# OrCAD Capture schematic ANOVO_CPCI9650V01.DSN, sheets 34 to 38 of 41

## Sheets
34 -DUAL POWER: size C; title: 34--CPCI hot swap
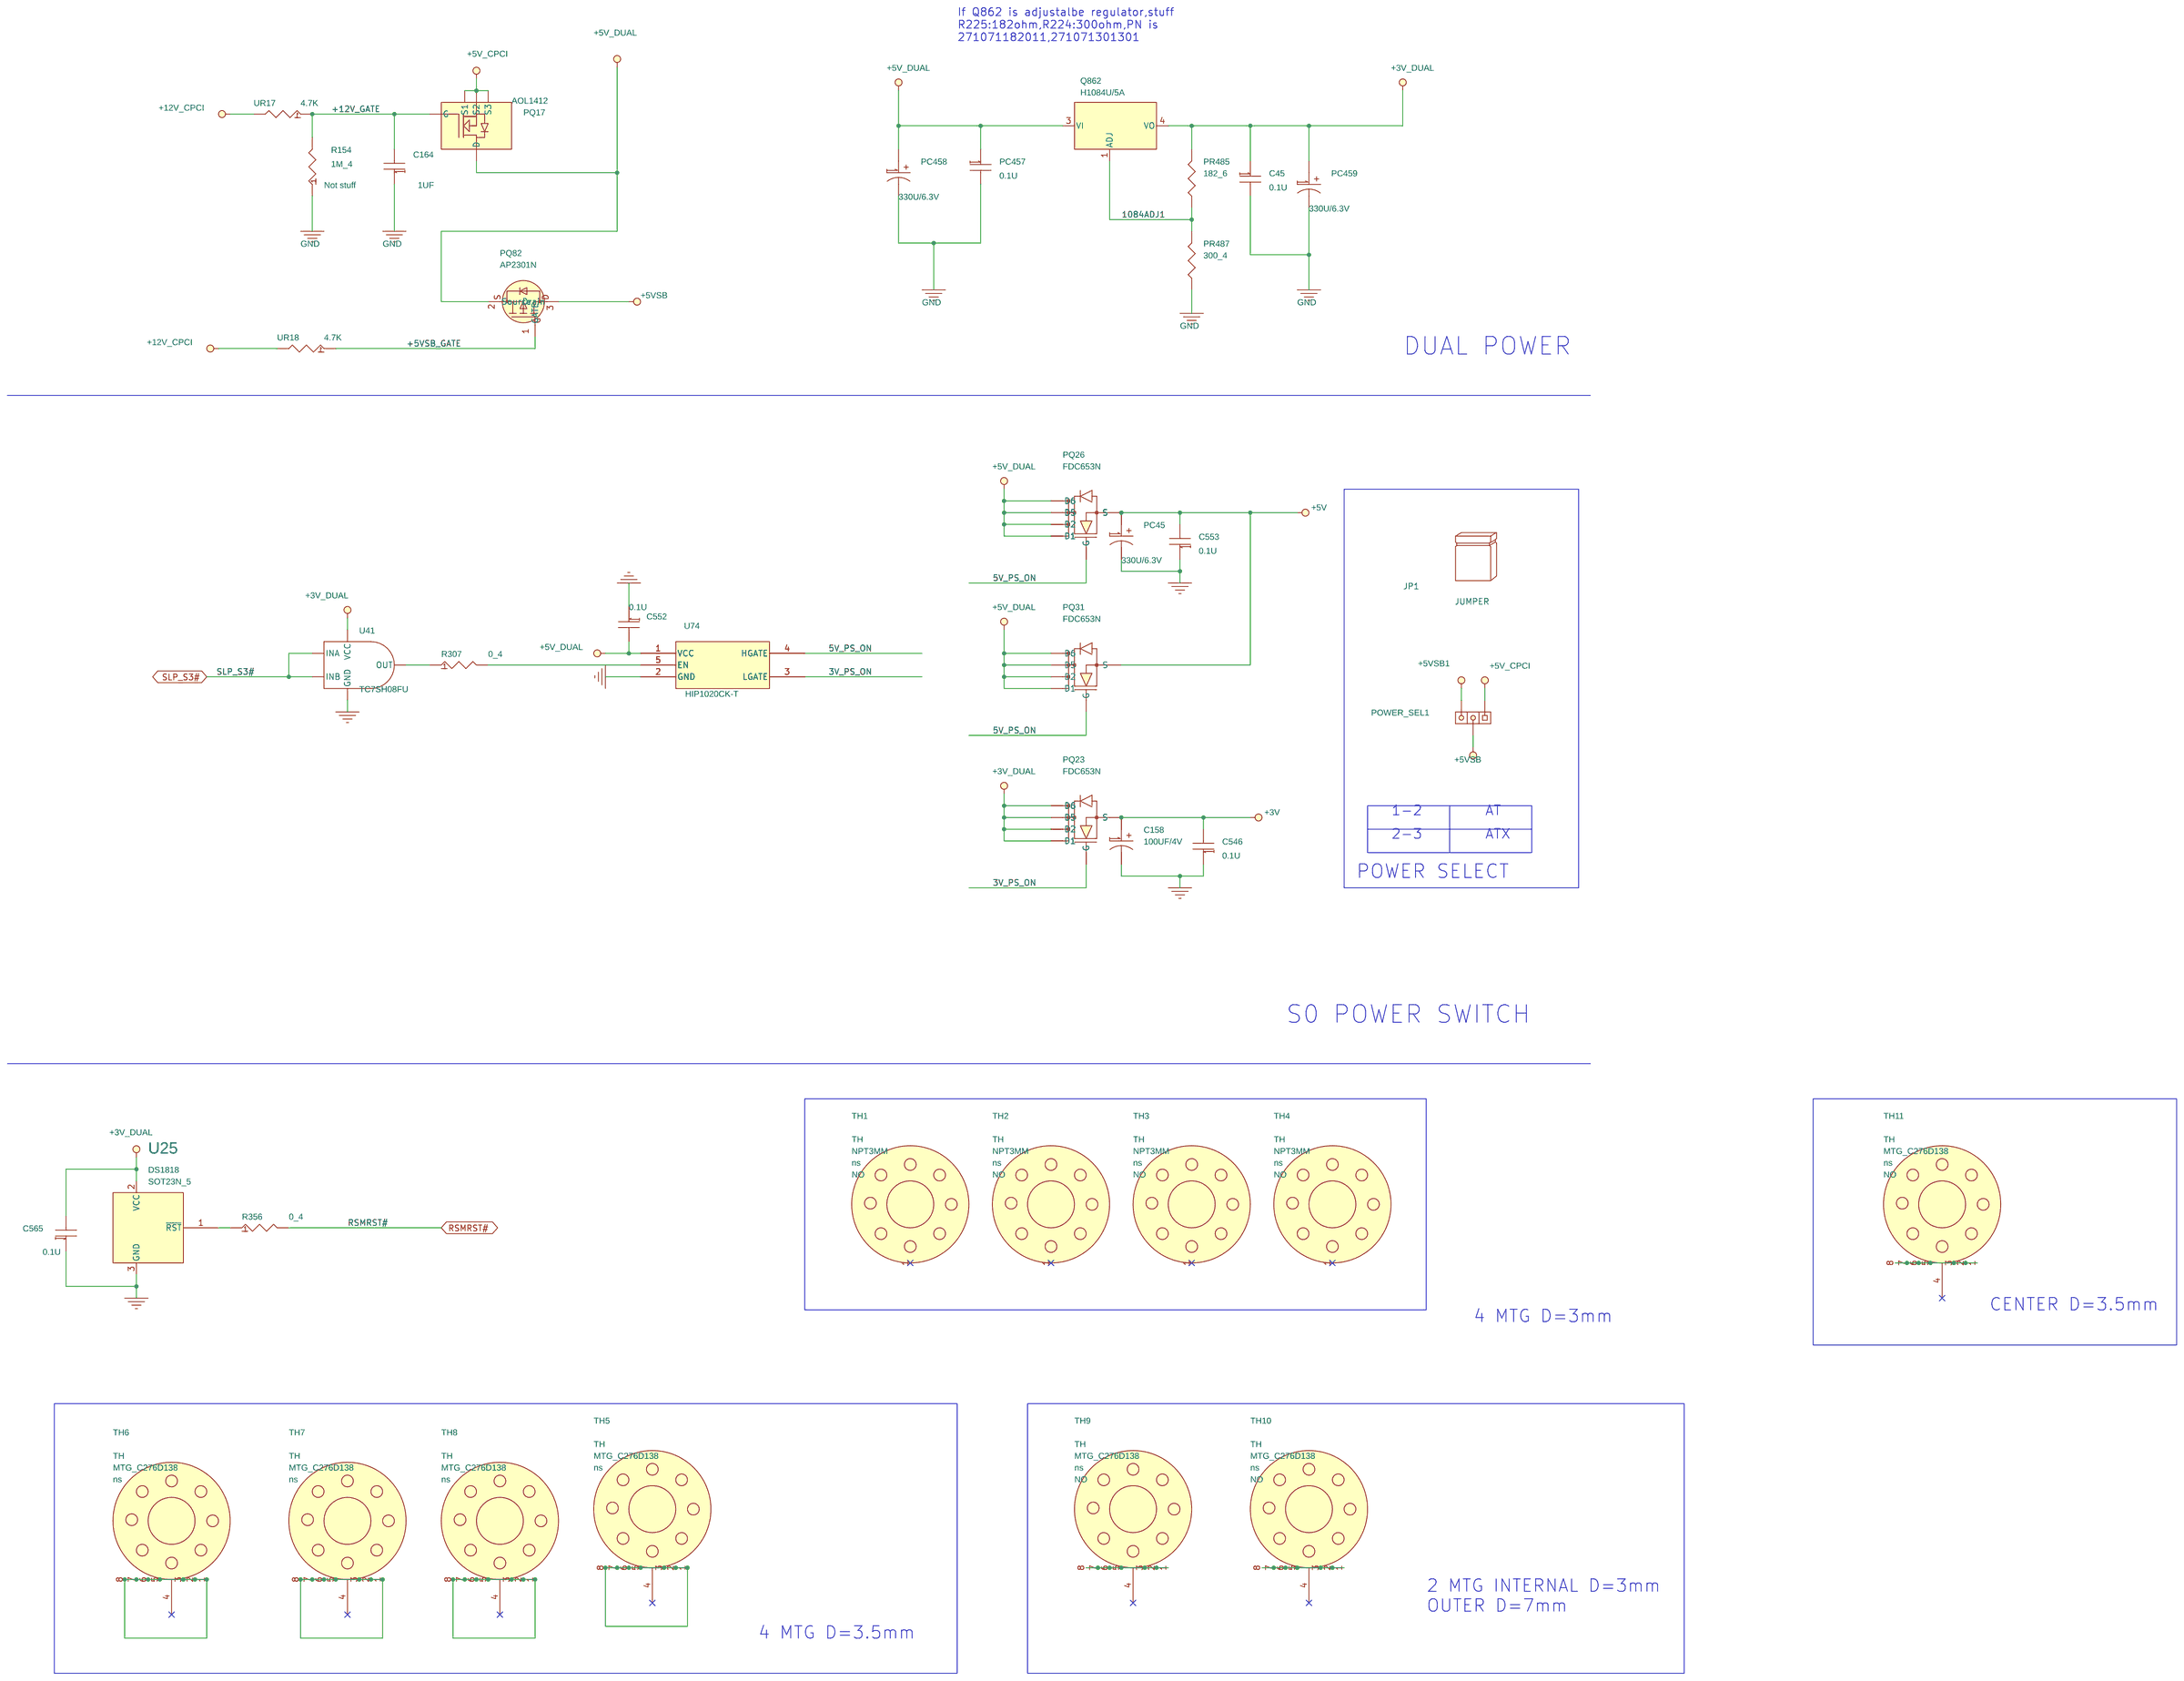
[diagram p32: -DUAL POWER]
35 -CH7307 DVI: size C
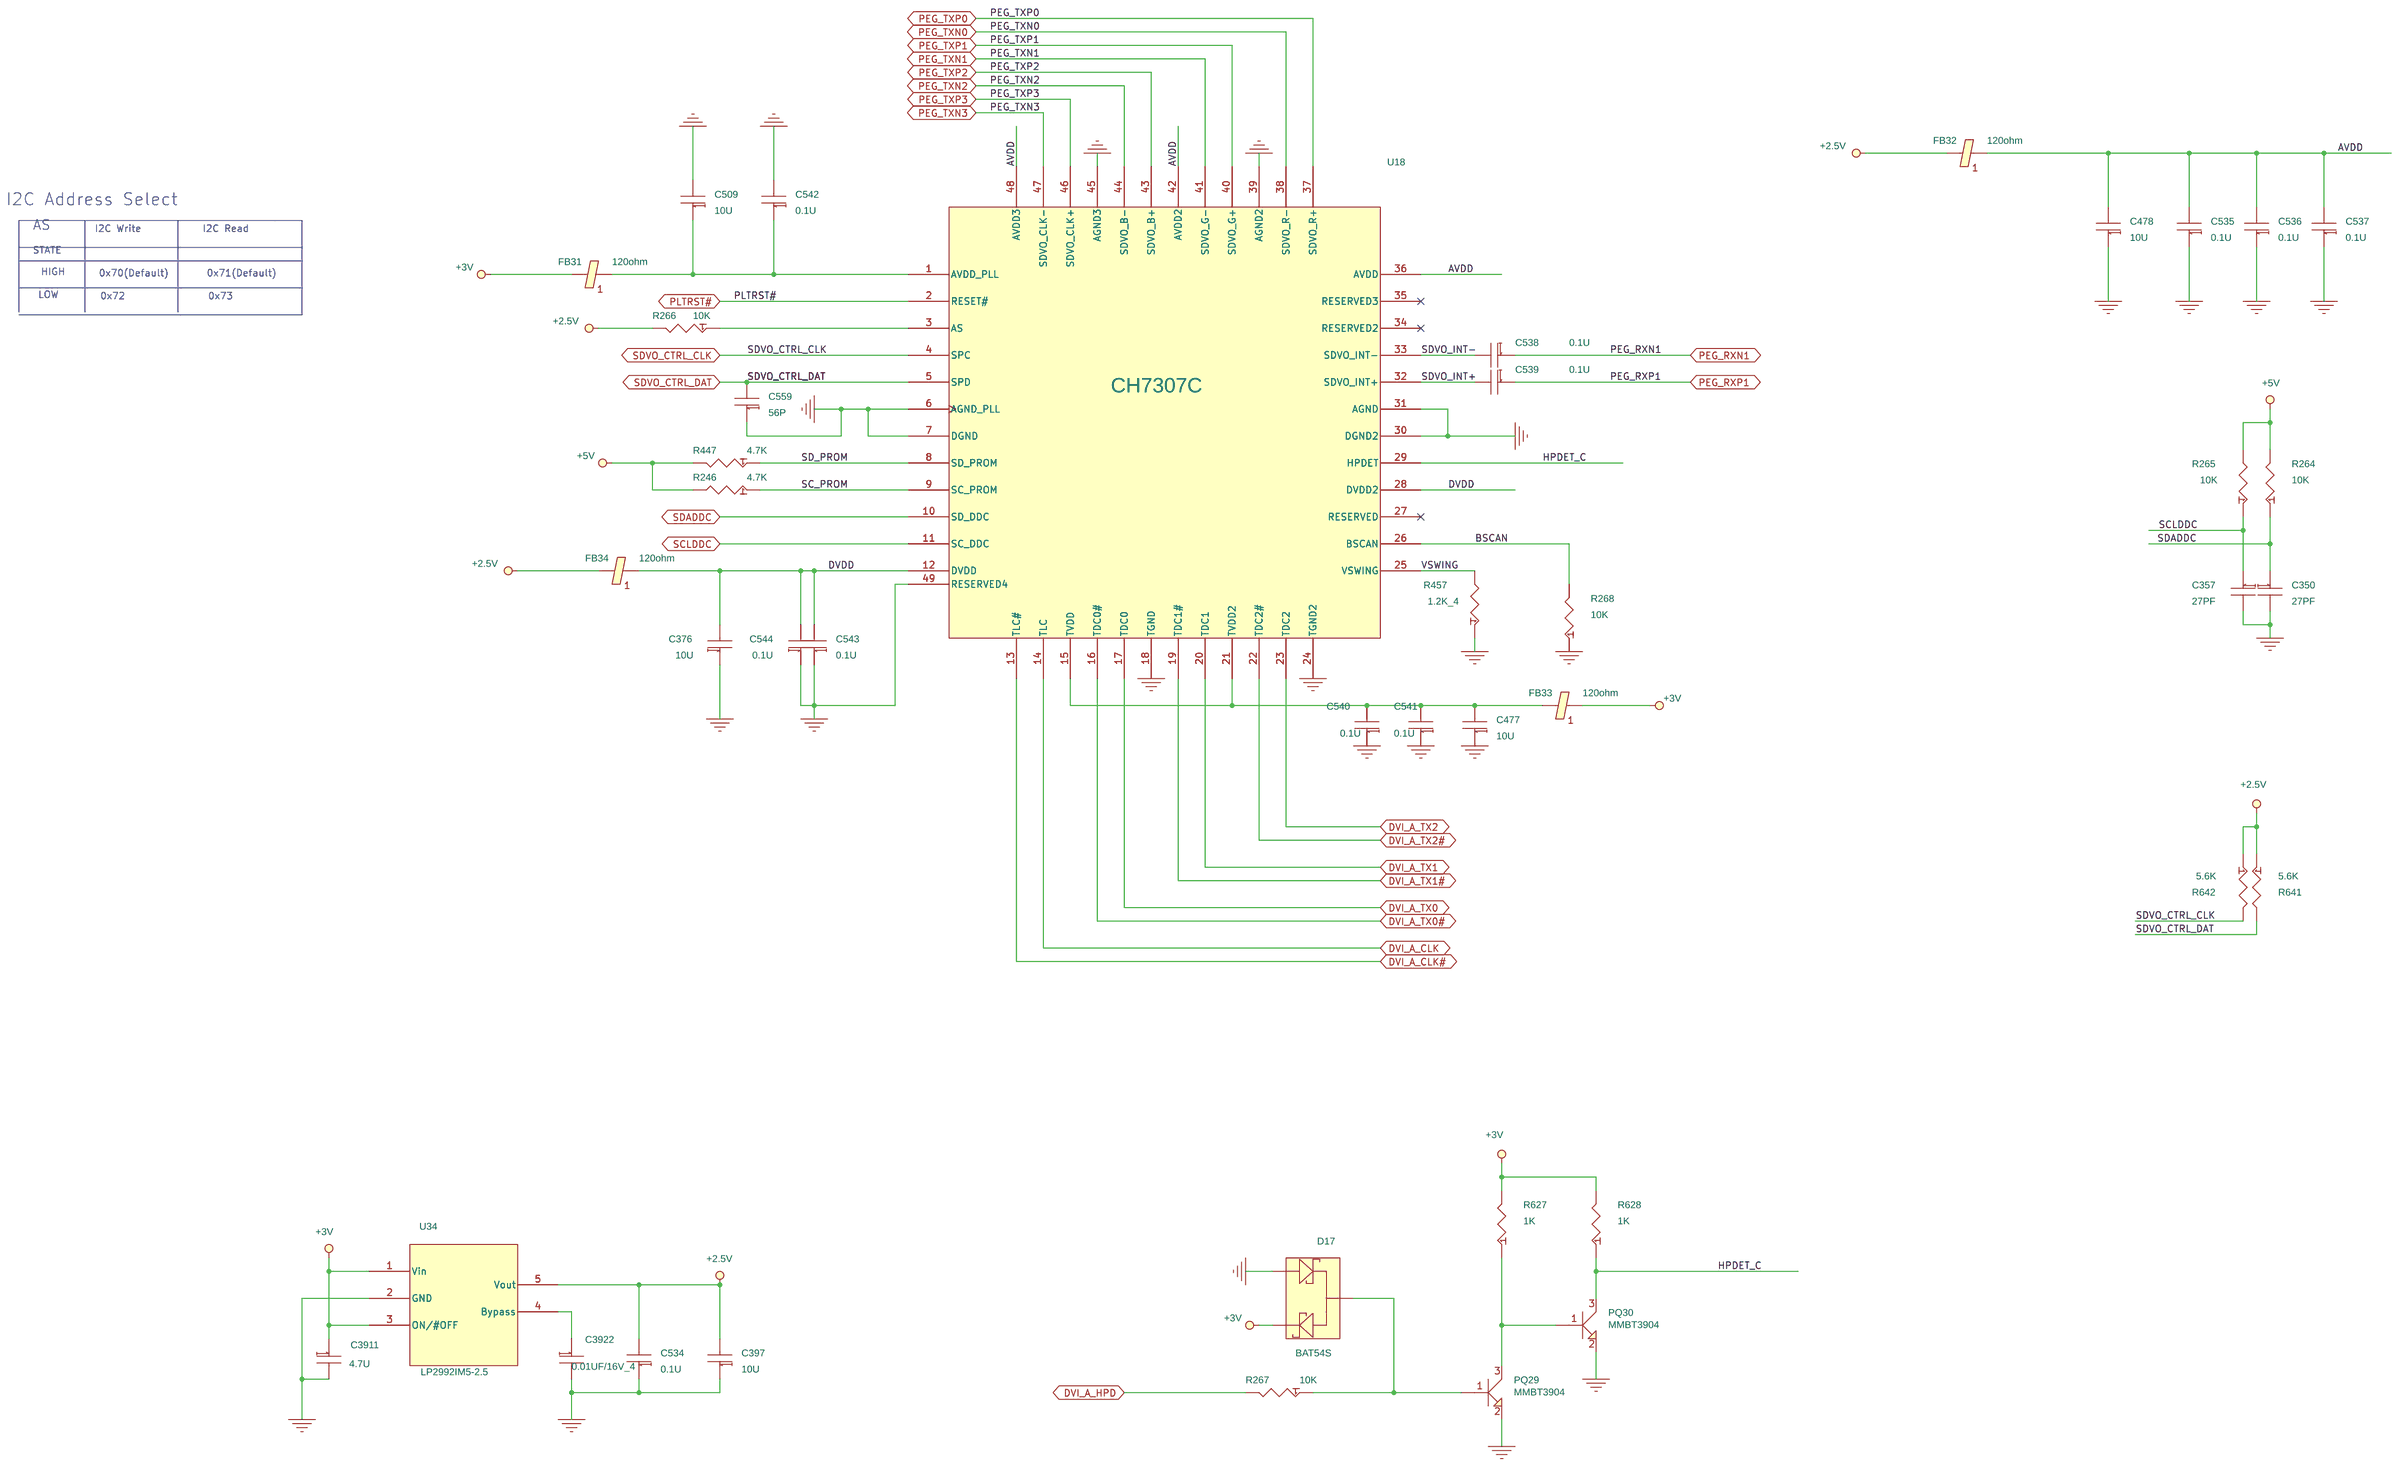
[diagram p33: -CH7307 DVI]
36 -POWER BLOCK &PWR ON: size C
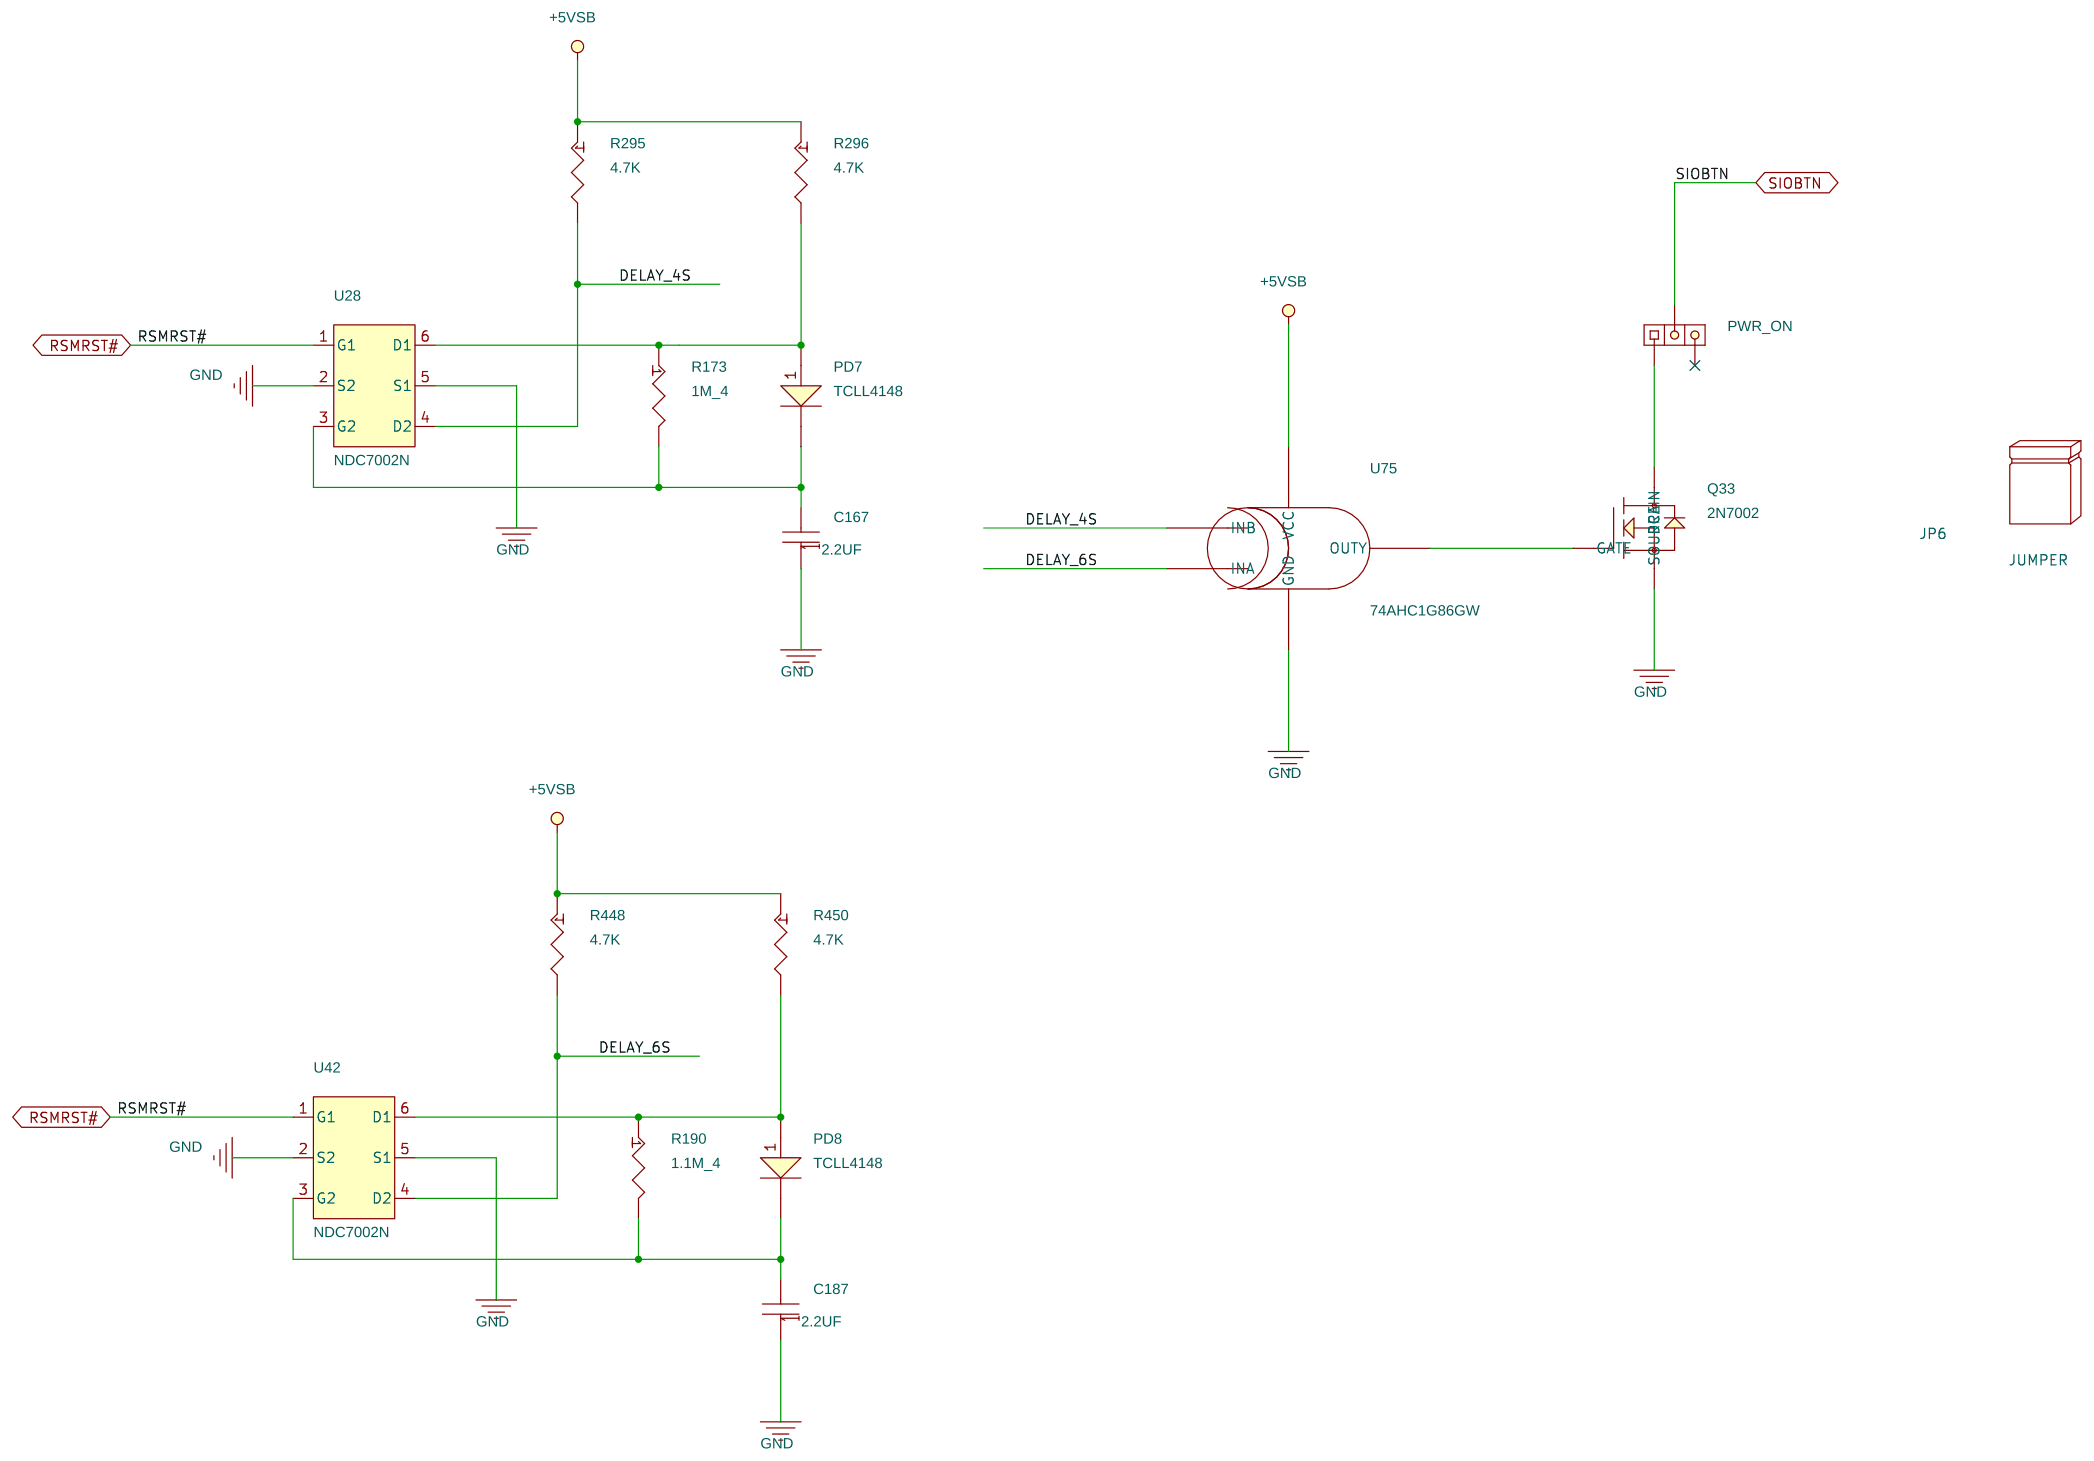
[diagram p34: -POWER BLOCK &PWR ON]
37 -ON BOARD DDR2 TERMINATIONS: size B; title: ON BOARD DDR2 TERMINATIONS
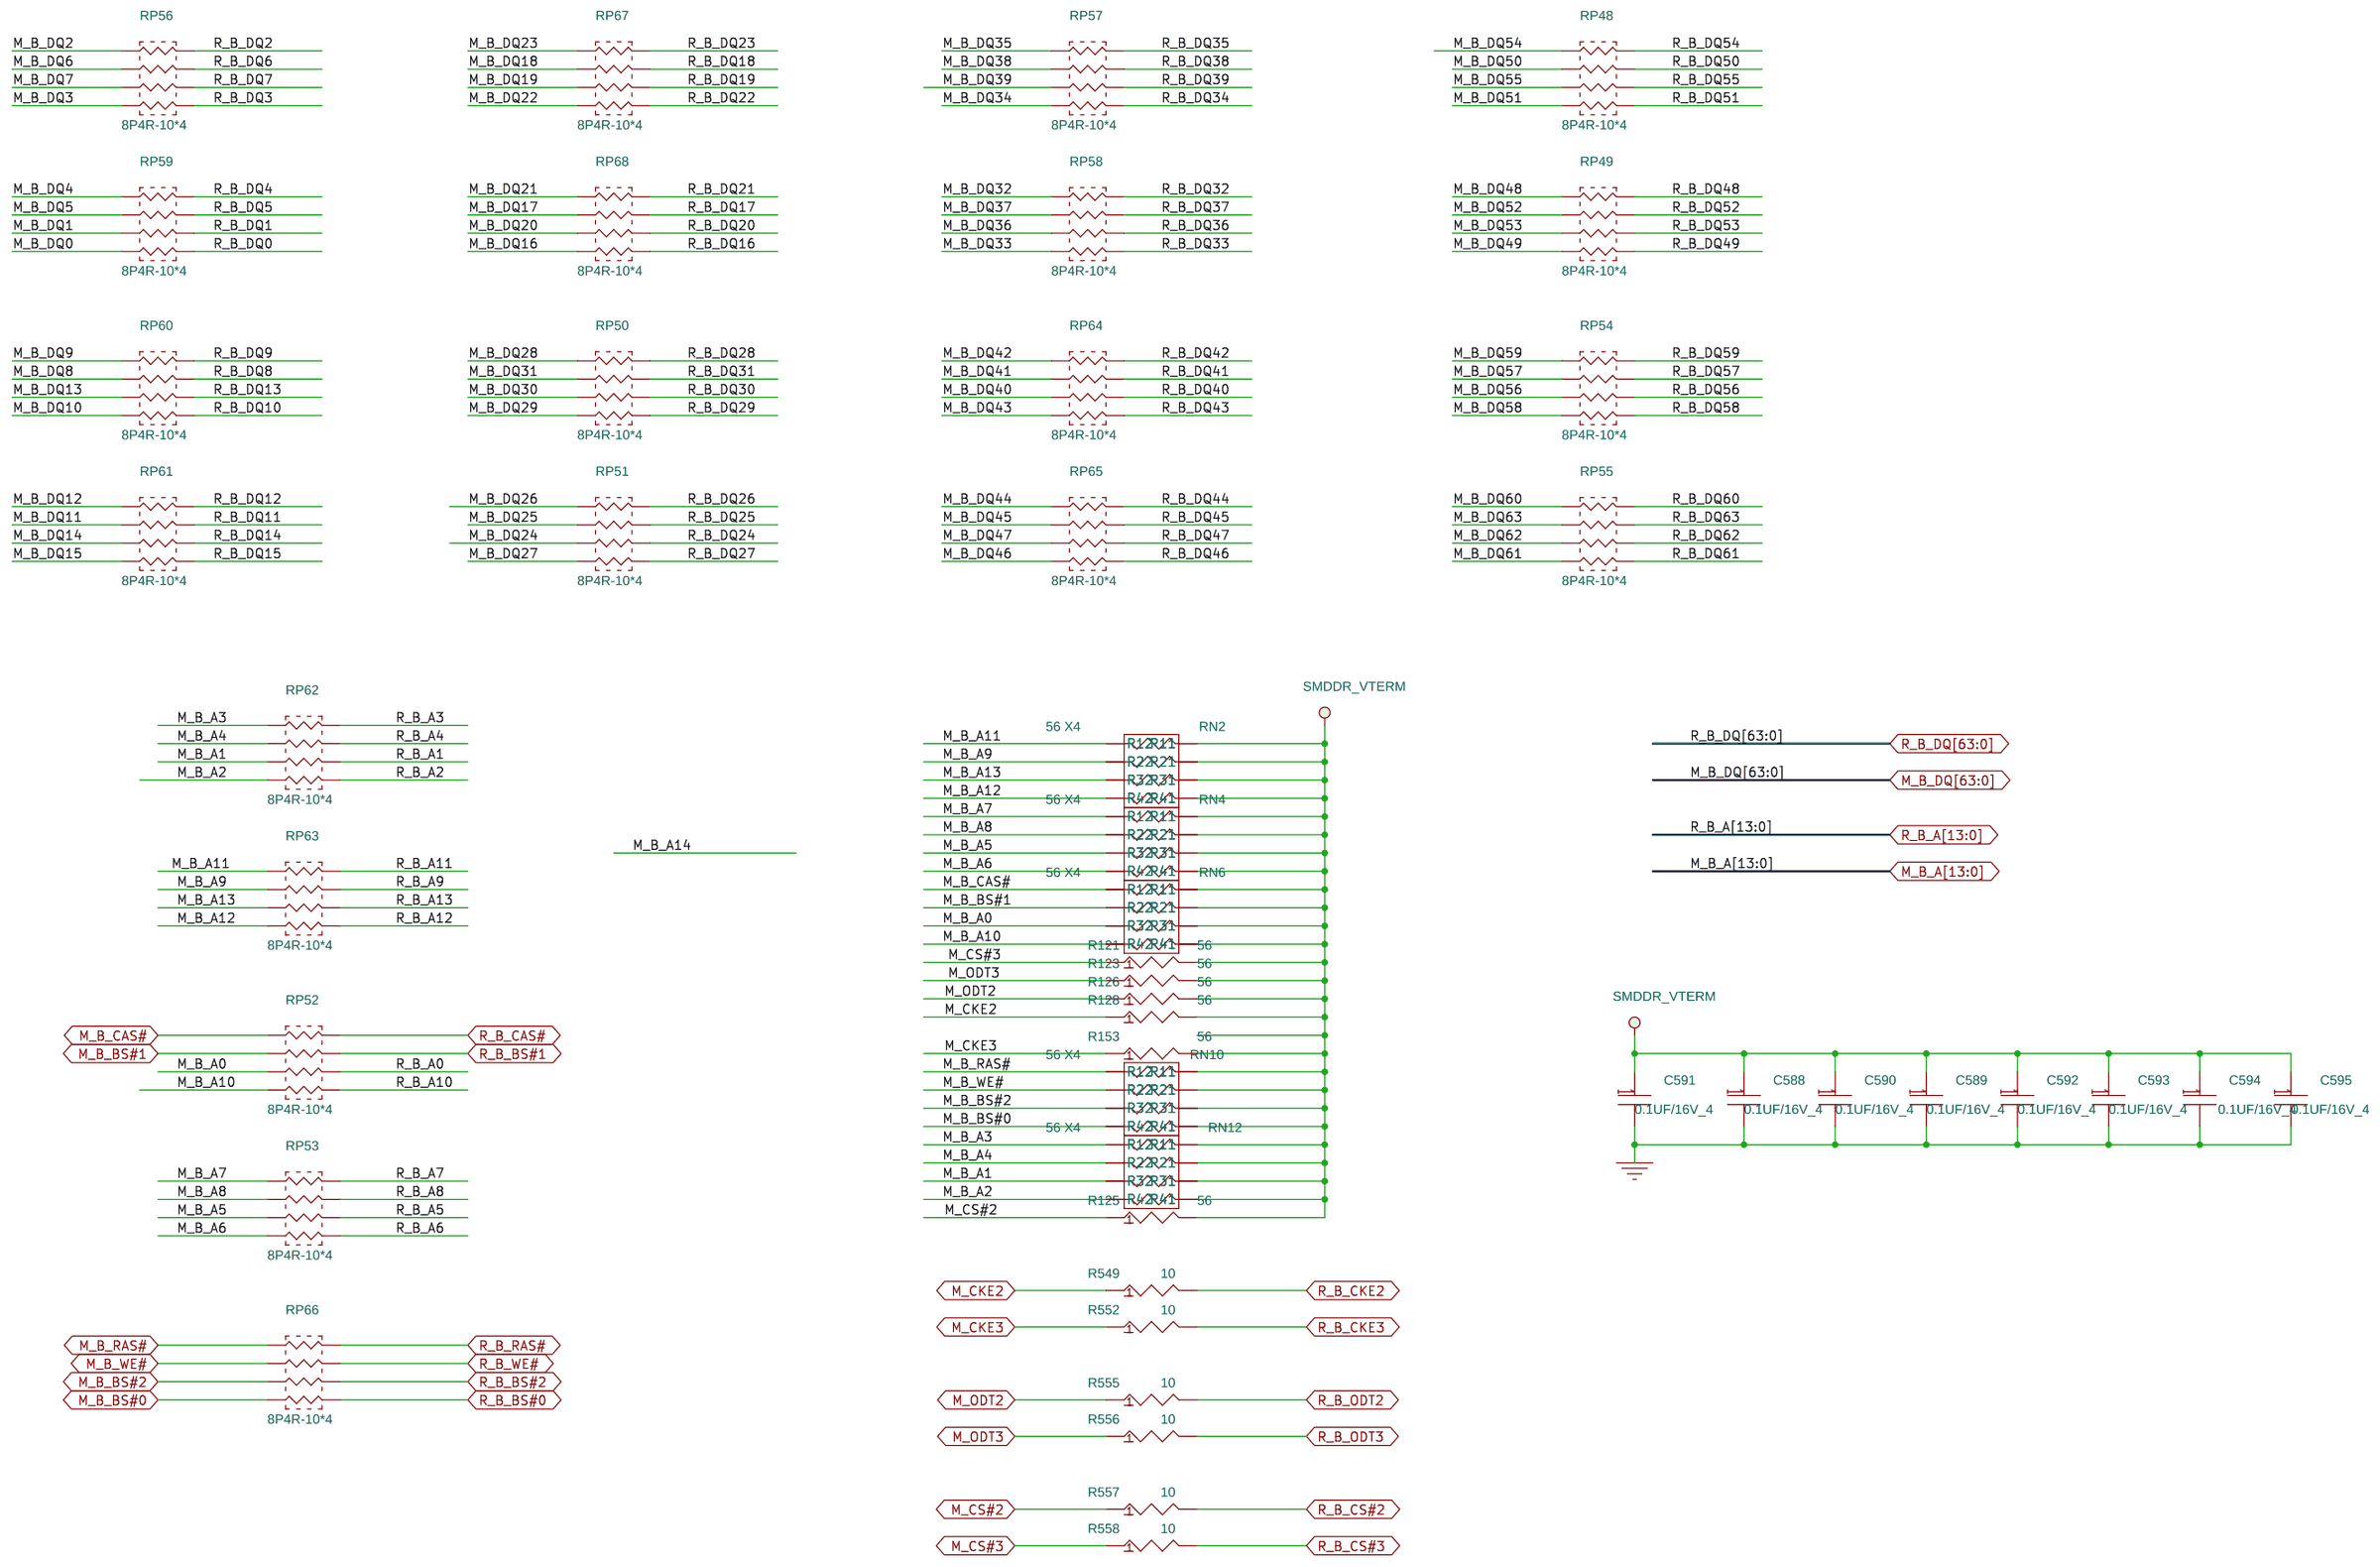
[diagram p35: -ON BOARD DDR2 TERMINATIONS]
38 -ON BOARD DDRII B0: size D; title: ON BOARD DDRII B0
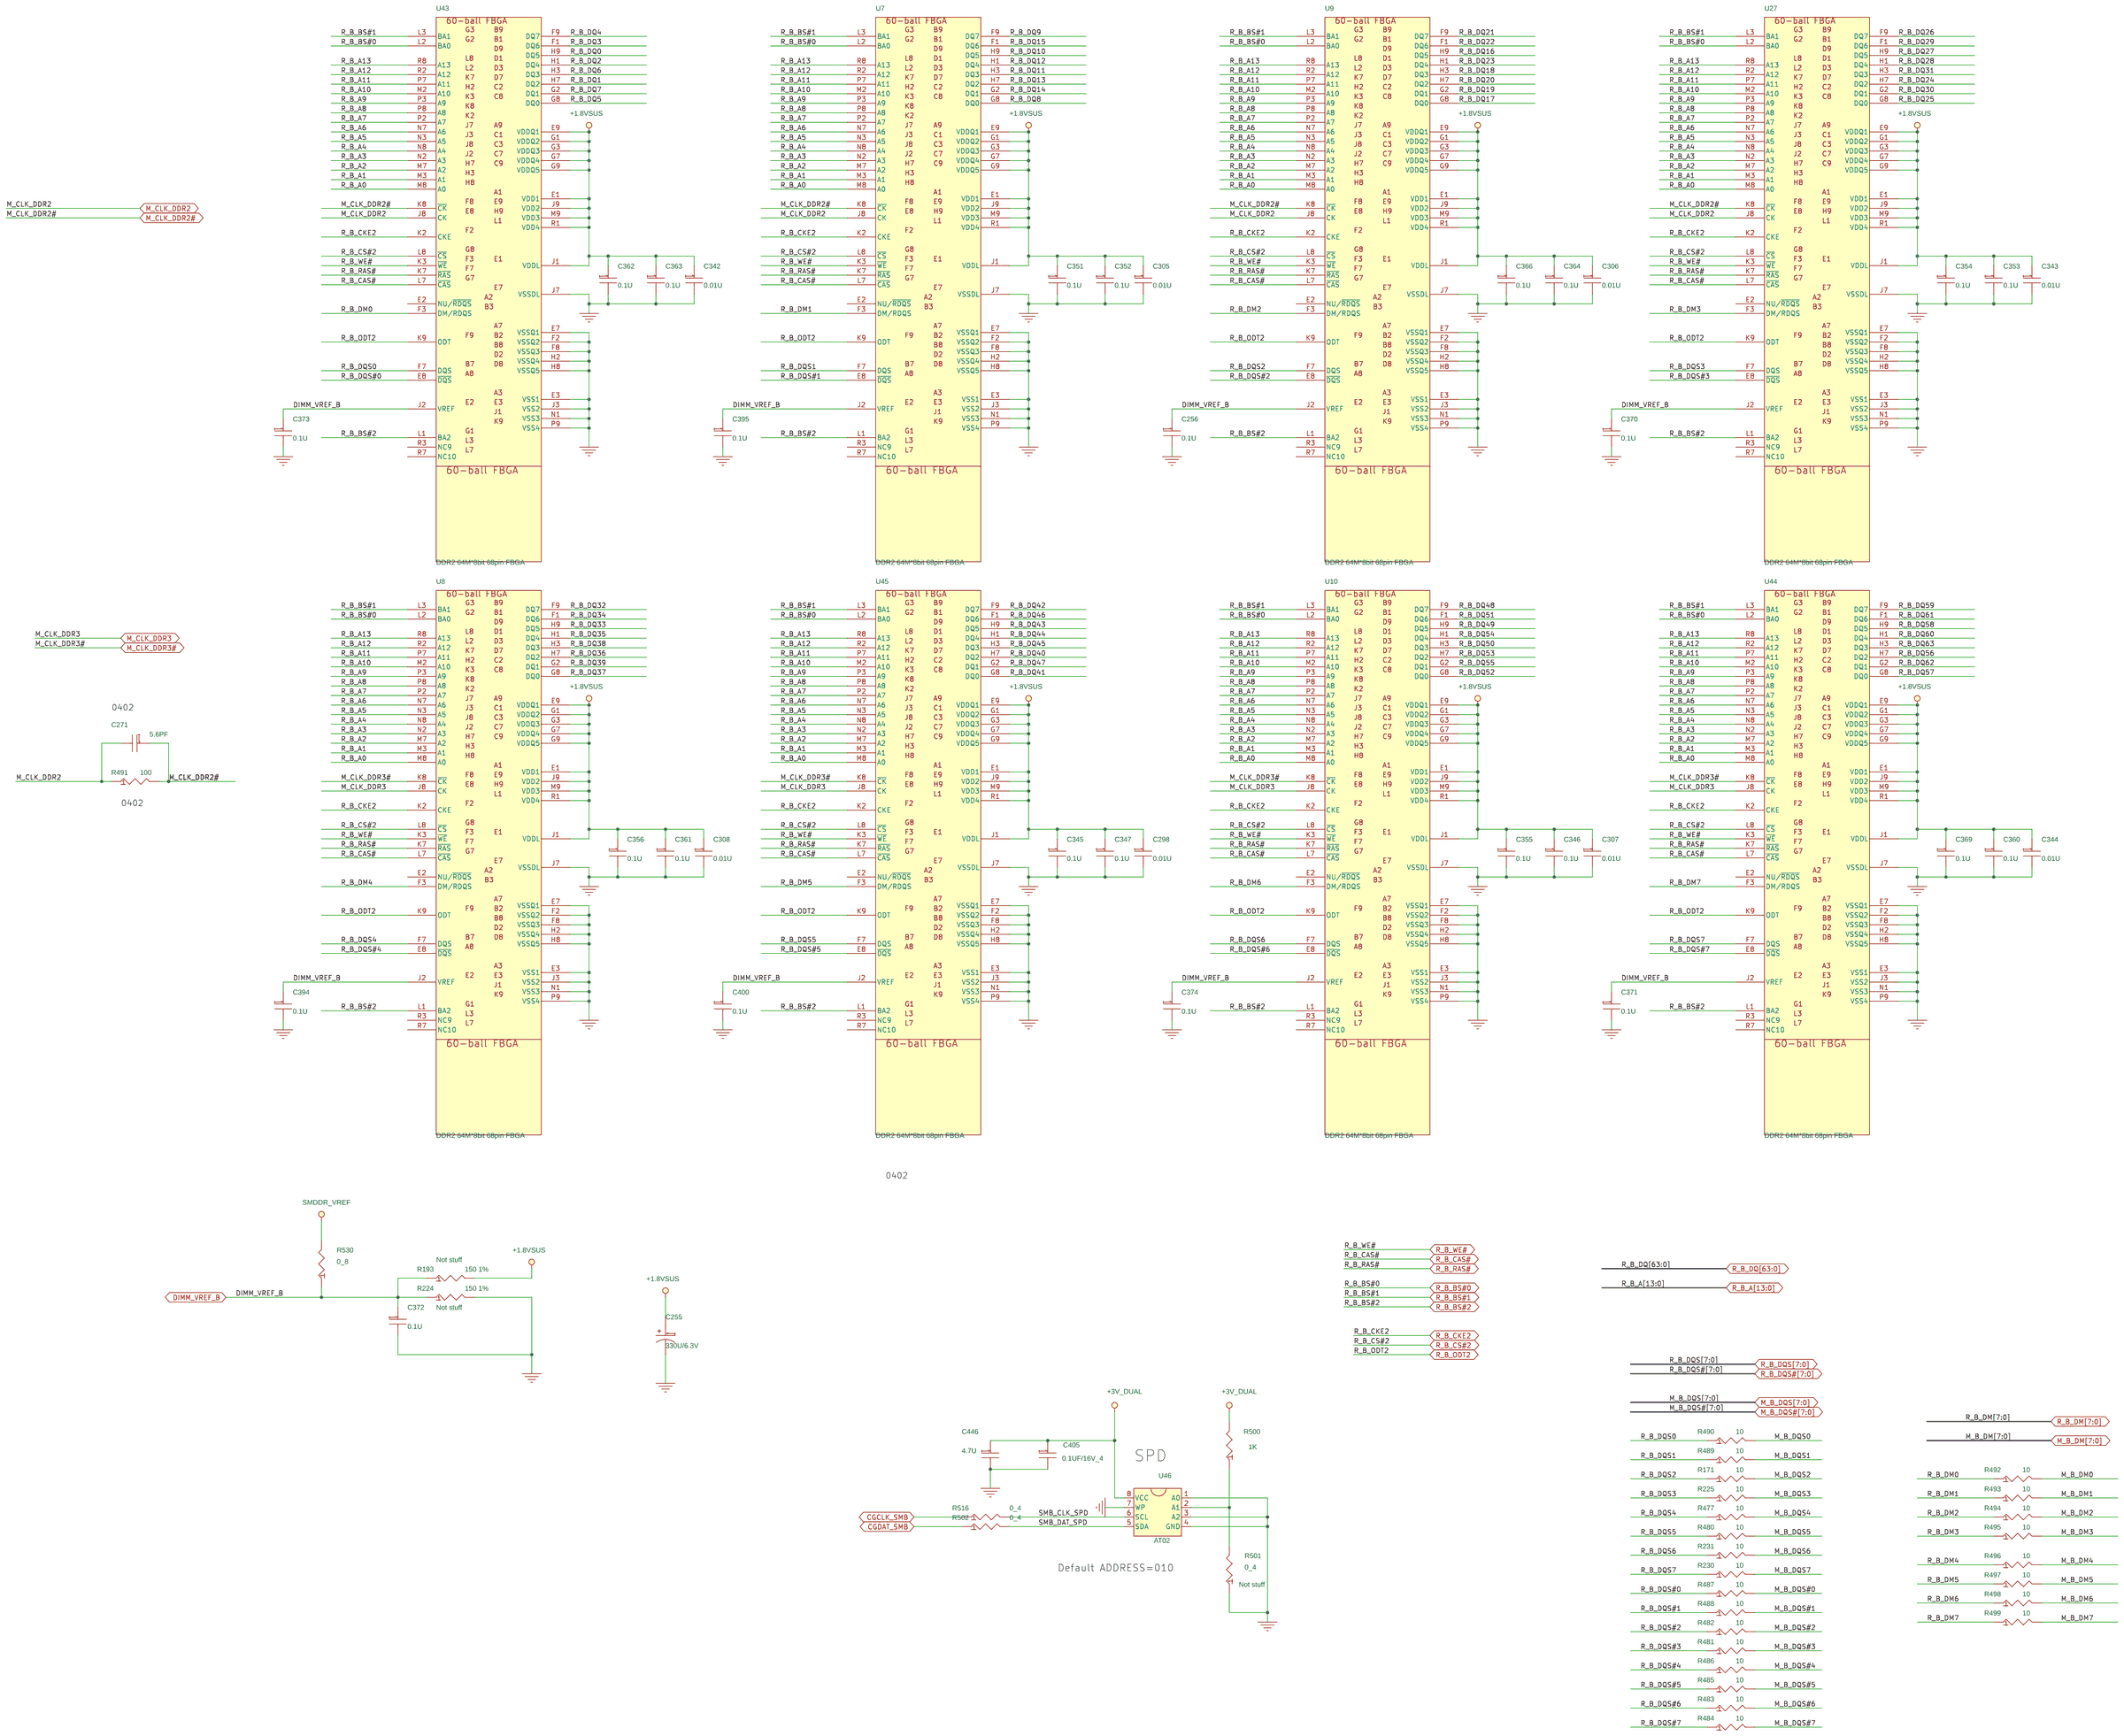
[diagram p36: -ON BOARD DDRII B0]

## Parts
sheet -CH7307 DVI
C350  27PF  [0402D]
C357  27PF  [0402D]
C376  10U  [0805D]
C397  10U  [0805D]
C477  10U  [0805D]
C478  10U  [0805D]
C509  10U  [0805D]
C534  0.1U  [0402D]
C535  0.1U  [0402D]
C536  0.1U  [0402D]
C537  0.1U  [0402D]
C538  0.1U  [0402D]
C539  0.1U  [0402D]
C540  0.1U  [0402D]
C541  0.1U  [0402D]
C542  0.1U  [0402D]
C543  0.1U  [0402D]
C544  0.1U  [0402D]
C559  56P  [0603D]
C3911  4.7U  [0805D]
C3922  0.01UF/16V_4  [0402D]
D17  BAT54S  [SOT23N_5]
FB31  120ohm  [0603D]
FB32  120ohm  [0603D]
FB33  120ohm  [0603D]
FB34  120ohm  [0603D]
PQ29  MMBT3904  [SOT23N_5]
PQ30  MMBT3904  [SOT23N_5]
R246  4.7K  [0402D]
R264  10K  [0402D]
R265  10K  [0402D]
R266  10K  [0402D]
R267  10K  [0402D]
R268  10K  [0402D]
R447  4.7K  [0402D]
R457  1.2K_4  [0402D]
R627  1K  [0402D]
R628  1K  [0402D]
R641  5.6K  [0603D]
R642  5.6K  [0603D]
U18  CH7307C  [ch7307x48-4-0729]
U34  LP2992IM5-2.5  [SSOP5-P-A-TOSHIBA]
sheet -DUAL POWER
C45  0.1U  [0402D]
C158  100UF/4V  [C3530]
C164  1UF  [0603D]
C546  0.1U  [0402D]
C552  0.1U  [0402D]
C553  0.1U  [0402D]
C565  0.1U  [0402D]
JP1  JUMPER
PC45  330U/6.3V  [1812A]
PC457  0.1U  [0402D]
PC458  330U/6.3V  [1812A]
PC459  330U/6.3V  [1812A]
POWER_SEL1  1x3 PIN  [conn_3b]
PQ17  AOL1412  [SO_8FL_5P_OA]
PQ23  FDC653N  [SSOT6-2_8-95]
PQ26  FDC653N  [SSOT6-2_8-95]
PQ31  FDC653N  [SSOT6-2_8-95]
PQ82  AP2301N  [SOT23N_5]
PR485  182_6  [0603D]
PR487  300_4  [0402D]
Q862  H1084U/5A  [SOT252NP2]
R154  1M_4  [0402D]
R307  0_4  [0402D]
R356  0_4  [0402D]
TH1  TH  [NPT3MM]
TH2  TH  [NPT3MM]
TH3  TH  [NPT3MM]
TH4  TH  [NPT3MM]
TH5  TH  [MTG_C276D138]
TH6  TH  [MTG_C276D138]
TH7  TH  [MTG_C276D138]
TH8  TH  [MTG_C276D138]
TH9  TH  [MTG_C276D138]
TH10  TH  [MTG_C276D138]
TH11  TH  [MTG_C276D138]
U25  DS1818  [SOT23N_5]
U41  TC7SH08FU  [SSOP5_TOSHIBA]
U74  HIP1020CK-T  [sot23_5pin]
UR17  4.7K  [0402D]
UR18  4.7K  [0402D]
sheet -ON BOARD DDR2 TERMINATIONS
C588  0.1UF/16V_4  [0402D]
C589  0.1UF/16V_4  [0402D]
C590  0.1UF/16V_4  [0402D]
C591  0.1UF/16V_4  [0402D]
C592  0.1UF/16V_4  [0402D]
C593  0.1UF/16V_4  [0402D]
C594  0.1UF/16V_4  [0402D]
C595  0.1UF/16V_4  [0402D]
R121  56  [0402D]
R123  56  [0402D]
R125  56  [0402D]
R126  56  [0402D]
R128  56  [0402D]
R153  56  [0402D]
R549  10  [0402D]
R552  10  [0402D]
R555  10  [0402D]
R556  10  [0402D]
R557  10  [0402D]
R558  10  [0402D]
RN2  56 X4  [RP_8P4R_0804B]
RN4  56 X4  [RP_8P4R_0804B]
RN6  56 X4  [RP_8P4R_0804B]
RN10  56 X4  [RP_8P4R_0804B]
RN12  56 X4  [RP_8P4R_0804B]
RP48  8P4R-10*4  [RP_8P4R_0804B]
RP49  8P4R-10*4  [RP_8P4R_0804B]
RP50  8P4R-10*4  [RP_8P4R_0804B]
RP51  8P4R-10*4  [RP_8P4R_0804B]
RP52  8P4R-10*4  [RP_8P4R_0804B]
RP53  8P4R-10*4  [RP_8P4R_0804B]
RP54  8P4R-10*4  [RP_8P4R_0804B]
RP55  8P4R-10*4  [RP_8P4R_0804B]
RP56  8P4R-10*4  [RP_8P4R_0804B]
RP57  8P4R-10*4  [RP_8P4R_0804B]
RP58  8P4R-10*4  [RP_8P4R_0804B]
RP59  8P4R-10*4  [RP_8P4R_0804B]
RP60  8P4R-10*4  [RP_8P4R_0804B]
RP61  8P4R-10*4  [RP_8P4R_0804B]
RP62  8P4R-10*4  [RP_8P4R_0804B]
RP63  8P4R-10*4  [RP_8P4R_0804B]
RP64  8P4R-10*4  [RP_8P4R_0804B]
RP65  8P4R-10*4  [RP_8P4R_0804B]
RP66  8P4R-10*4  [RP_8P4R_0804B]
RP67  8P4R-10*4  [RP_8P4R_0804B]
RP68  8P4R-10*4  [RP_8P4R_0804B]
sheet -ON BOARD DDRII B0
C255  330U/6.3V  [1812A]
C256  0.1U  [0402D]
C271  5.6PF  [0402D]
C298  0.01U  [0402D]
C305  0.01U  [0402D]
C306  0.01U  [0402D]
C307  0.01U  [0402D]
C308  0.01U  [0402D]
C342  0.01U  [0402D]
C343  0.01U  [0402D]
C344  0.01U  [0402D]
C345  0.1U  [0402D]
C346  0.1U  [0402D]
C347  0.1U  [0402D]
C351  0.1U  [0402D]
C352  0.1U  [0402D]
C353  0.1U  [0402D]
C354  0.1U  [0402D]
C355  0.1U  [0402D]
C356  0.1U  [0402D]
C360  0.1U  [0402D]
C361  0.1U  [0402D]
C362  0.1U  [0402D]
C363  0.1U  [0402D]
C364  0.1U  [0402D]
C366  0.1U  [0402D]
C369  0.1U  [0402D]
C370  0.1U  [0402D]
C371  0.1U  [0402D]
C372  0.1U  [0402D]
C373  0.1U  [0402D]
C374  0.1U  [0402D]
C394  0.1U  [0402D]
C395  0.1U  [0402D]
C400  0.1U  [0402D]
C405  0.1UF/16V_4  [0402D]
C446  4.7U  [0805D]
R171  10  [0402D]
R193  150 1%  [0402D]
R224  150 1%  [0402D]
R225  10  [0402D]
R230  10  [0402D]
R231  10  [0402D]
R477  10  [0402D]
R480  10  [0402D]
R481  10  [0402D]
R482  10  [0402D]
R483  10  [0402D]
R484  10  [0402D]
R485  10  [0402D]
R486  10  [0402D]
R487  10  [0402D]
R488  10  [0402D]
R489  10  [0402D]
R490  10  [0402D]
R491  100  [0402D]
R492  10  [0402D]
R493  10  [0402D]
R494  10  [0402D]
R495  10  [0402D]
R496  10  [0402D]
R497  10  [0402D]
R498  10  [0402D]
R499  10  [0402D]
R500  1K  [0402D]
R501  0_4  [0402D]
R502  0_4  [0402D]
R516  0_4  [0402D]
R530  0_8  [0805D]
U7  DDR2 64M*8bit 68pin FBGA  [fbga60]
U8  DDR2 64M*8bit 68pin FBGA  [fbga60]
U9  DDR2 64M*8bit 68pin FBGA  [fbga60]
U10  DDR2 64M*8bit 68pin FBGA  [fbga60]
U27  DDR2 64M*8bit 68pin FBGA  [fbga60]
U43  DDR2 64M*8bit 68pin FBGA  [fbga60]
U44  DDR2 64M*8bit 68pin FBGA  [fbga60]
U45  DDR2 64M*8bit 68pin FBGA  [fbga60]
U46  AT02  [SOIC8]
sheet -POWER BLOCK &PWR ON
C167  2.2UF  [0603D]
C187  2.2UF  [0603D]
JP6  JUMPER
PD7  TCLL4148  [DC1506N]
PD8  TCLL4148  [DC1506N]
PWR_ON  1x3 PIN  [conn_3b]
Q33  2N7002  [SOT23N_5]
R173  1M_4  [0402D]
R190  1.1M_4  [0402D]
R295  4.7K  [0402D]
R296  4.7K  [0402D]
R448  4.7K  [0402D]
R450  4.7K  [0402D]
U28  NDC7002N  [TSOP6]
U42  NDC7002N  [TSOP6]
U75  74AHC1G86GW  [SSOP5_TOSHIBA]

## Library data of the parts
C350 C357 = CAP_NP: ANOVO DESCRIPTION: CAP;27P ,16V ,5% ,0402 ,NPO ,SMT; ANOVO PART NUMBER: 272043270101; BACKSIDE: 0; Part Type: CCAP; SMT: YES
C376 C397 C477 C478 C509 = CAP_NP: ANOVO DESCRIPTION: CAP;10U,10V,+80-20%,0805,Y5V,SMT; ANOVO PART NUMBER: 272002106401; Part Type: CCAP
C45 C534-C544 C546 C553 PC457 = CAP_NP: ANOVO DESCRIPTION: CAP;0.1U ,16V ,10% ,0402 ,X7R ,SMT; ANOVO PART NUMBER: 272043104201; Part Type: CCAP
C559 = CAP_NP: ANOVO DESCRIPTION: CAP;56P ,50V ,5% ,0603 ,NPO ,SMT; ANOVO PART NUMBER: 272075560101; Part Type: CCAP
C446 C3911 = CAP_NP: ANOVO DESCRIPTION: CAP;4.7U ,10V ,+80-20% ,0805 ,Y5V ,SMT; ANOVO PART NUMBER: 272002475401; Part Type: CCAP
C3922 = CAP_NP: ANOVO DESCRIPTION: CAP,0.01U  ,CR,16V,+80-20%,0402,Y5V,SMT; ANOVO PART NUMBER: 272043103201; BACKSIDE: 0; Part Type: CCAP; ROOM: CPU; SMT: YES
D17 = BAT54S: ANOVO DESCRIPTION: DIODE;BAT54S,SCHOTTKY DIODE,SOT23; ANOVO PART NUMBER: 288100054021; BACKSIDE: 0; Part Type: SCHOTTKY; SMT: YES; Datasheet: \\Rdserver\norcocis\datasheet\DIODE\fairchild\BAT54.pdf
FB31-FB34 = FERRITE_BEAD: ANOVO DESCRIPTION: FERRITE CHIP;120 OHM/100MHZ,0603,600MA,SMT; ANOVO PART NUMBER: 273001213200; BACKSIDE: 0; Part Type: FERRITE BEAD; SMT: YES
PQ29 PQ30 = NPN: ANOVO DESCRIPTION: TRANS;MMBT3904,NPN,40V,200mA,SOT23; ANOVO PART NUMBER: 288203904001; BACKSIDE: 0; Part Type: TRANSISTOR; SMT: YES; Datasheet: \\Rdserver\norcocis\datasheet\transistor\fairchild\MMBT3904.pdf
R246 R295 R296 R447 R448 R450 UR17 UR18 = R_v2: ANOVO DESCRIPTION: RES;4.7K ,1/16W ,5% ,0402 ,SMT; ANOVO PART NUMBER: 271040472301; Part Type: RESISTOR
R264-R268 = R_v2: ANOVO DESCRIPTION: RES;10K ,1/16W ,5% ,0402 ,SMT; ANOVO PART NUMBER: 271040103301; BACKSIDE: 0; Part Type: RESISTOR; SMT: YES
R457 = R_v2: ANOVO DESCRIPTION: RES;1.2K ,1/16W ,1% ,0402 ,SMT; ANOVO PART NUMBER: 271040122101; Part Type: RESISTOR
R500 R627 R628 = R_v2: ANOVO DESCRIPTION: RES;1K ,1/16W ,1% ,0402 ,SMT; ANOVO PART NUMBER: 271040102101; Part Type: RESISTOR
R641 R642 = R_v2: ANOVO DESCRIPTION: RES;5.6K ,1/16W,5% ,0603,SMT; ANOVO PART NUMBER: 271071562301
U18 = ALC880-M-LQFP48_1: 8ND PART FIELD: TOP; ANOVO DESCRIPTION: IC;CH7307C,CHRONTEL SDVO DVI Transmitter,LQFP 48P; ANOVO PART NUMBER: 286307307001; ROOM: AUDIO
U34 = LP2992: ANOVO DESCRIPTION: IC;LP2992IM5-2.5,2.5V REGULATOR,250mA,SOT-23; ANOVO PART NUMBER: 286402992001
C158 = CAP_T: ANOVO DESCRIPTION: TANCAP;100U ,4V,+-20%,C3530,SMT; ANOVO PART NUMBER: 272631070011; Part Type: TAN CAP
C164 C167 C187 = CAP_NP: ANOVO DESCRIPTION: CAP;0.22U ,16V ,10% ,0603 ,X7R ,SMT; ANOVO PART NUMBER: 272073224201; BACKSIDE: 0; Part Type: CCAP; SMT: YES
C552 C565 = CAP_NP: ANOVO DESCRIPTION: CAP;0.1U ,16V ,10% ,0402 ,X7R ,SMT; ANOVO PART NUMBER: 272043104201; BACKSIDE: 0; Part Type: CCAP; SMT: YES
JP1 JP6 = JUMPER: JUMPER COLOR BULE A TYPE; ANOVO DESCRIPTION: Jumper;Black;Plastic;2.54mm;Lotes; ANOVO PART NUMBER: 342700254000; Date: 00-12-5; Device: 143000000; ID: 172; Part Number: 143000000; Part Type: attachment; ROOM: USEATX; SMT: NO
C255 PC45 PC458 PC459 = CAP_T: ANOVO DESCRIPTION: TANCAP,330U,6.3V,20%,D size, SMT; ANOVO PART NUMBER: 272633371011
POWER_SEL1 PWR_ON = HEADER_1x3: header 1x3 pin; ANOVO DESCRIPTION: CON;DIP;HDR;3P*1;2.54mm pitch;ST;Gold;Zhiwei; ANOVO PART NUMBER: 331010003000; Device: 131000001; Part Number: 131000001; ROOM: USEATX; SMT: NO
PQ17 = MOS-N_0: ANOVO DESCRIPTION: TRANS;AOL1412,N-MOSFET,3.9MOHM,30V,85A,SO-8,Alpha & Omega Semiconductor; ANOVO PART NUMBER: 288221412001
PQ23 PQ26 PQ31 = SI3442DV_0: TRANSISTOR MOSFET FDC653N(30V,4.8A); 2ND PART FIELD: BAM653N0Z03; 8ND PART FIELD: TOP; ANOVO DESCRIPTION: TRANS,FDC653N,NPN,30V,4.8A,SSOT6,SMT; ANOVO PART NUMBER: 288200653001; COST NT$: 0; COST US$: 0; Dell Function Code: PWR.Support; Function Code: DCD; LAYER: TOP; Part Number: BAM653N0Z03; Quanta Function Code: DCD
PQ82 = P_MOS_SOT23: ANOVO DESCRIPTION: TRANS;AP2301N,P-MOSFET,-20V,-2.3A,130MOHM,SOT23,APEC; ANOVO PART NUMBER: 288222301001
PR485 = R: anovo description: RES;120 ,1/10W ,1% ,0603 ,SMT; anovo part number: 271071121101
PR487 = R: anovo description: RES;200 ,1/16W ,1% , 0402 ,SMT; anovo part number: 271040201101
Q862 = LDO_0: ANOVO DESCRIPTION: IC;H1084U;5A;3.3V;REG;TO-263A;HI-SINCERITY; ANOVO PART NUMBER: 286301084050; BACKSIDE: 0; Part Type: REGULATOR; SMT: YES; Datasheet: \\Rdserver\norcocis\datasheet\REGULATOR\HSMC\H1084U.PDF
R154 = R_v2: ANOVO DESCRIPTION: RES;1M ,1/16W ,5% ,0402 ,SMT; ANOVO PART NUMBER: 271040105301; BACKSIDE: 0; DUMMY: Not stuff; Part Type: RESISTOR; SMT: YES
R307 R356 = R_v2: ANOVO DESCRIPTION: RES;0 ,1/16W ,5% ,0402 ,SMT; ANOVO PART NUMBER: 271040000301; ID: 42; Part Type: RESISTOR; SMT: YES
TH1-TH4 = TH_4: BACKCOMP: NO; BACKSIDE: NO; OPTION: ns
TH5-TH8 = TH_0: OPTION: ns
TH9-TH11 = TH_0: BACKCOMP: NO; BACKSIDE: NO; OPTION: ns
U25 = DS1813_0: ANOVO DESCRIPTION: IC;DS1818,RST CHIP FOR 150MS,3P,SOT23; ANOVO PART NUMBER: 282071818001
U41 = TC7SH08FU
U74 = HIP1020CK-T_0: ANOVO DESCRIPTION: IC;HIP1020CKZ-T,DUAL OUTPUT HOT PLUG CTRL,5P,SOT23; ANOVO PART NUMBER: 286401020001
C256 C345-C347 C351-C356 C360-C364 C366 C369-C374 C394 C395 C400 C405 C588-C595 = CAP_NP: ANOVO DESCRIPTION: CAP;0.1U ,16V ,+80-20% ,0402 ,Y5V ,SMT; ANOVO PART NUMBER: 272043104401; BACKSIDE: 0; Part Type: CCAP; SMT: YES
R121 R123 R125 R126 R128 R153 = R_v2: ANOVO DESCRIPTION: RES,56 ,1/16W ,5%, 0402, SMT; ANOVO PART NUMBER: 271040560301; BACKSIDE: 0; Part Type: RESISTOR
R171 R225 R230 R231 R477 R480-R490 R492-R499 R549 R552 R555-R558 = R_v2: RES;10 ,1/16W ,5% ,0402 ,SMT; ANOVO DESCRIPTION: RES;10 ,1/16W ,5% ,0402 ,SMT; ANOVO PART NUMBER: 271040100301; BACKCOMP: YES; Part Type: RESISTOR; SMT: YES
RN2 RN4 RN6 RN10 RN12 = R_8P4R: NETWORK 56 OHMX4 8PIN 0402 SMT; ANOVO DESCRIPTION: RP;56*4 ,8P ,1/16W ,5% ,0408,SMT; ANOVO PART NUMBER: 271590560301; BACKCOMP: NO; BACKSIDE: NO; ID: 459; Part Type: NETWORK; SMT: YES
RP48-RP68 = 10*4_3: RP,10*4 ,8P ,1/16W ,5% 0408 ,SMT; ANOVO DESCRIPTION: RP,10*4 ,8P ,1/16W ,5% 0408 ,SMT; ANOVO PART NUMBER: 271590100301
C271 = CAP_NP: ANOVO DESCRIPTION: CAP;5.6P ,50V , 5% ,0402 ,NPO ,SMT; ANOVO PART NUMBER: 272045056101; BACKSIDE: 0; Part Type: CCAP; SMT: YES
C298 C305-C308 C342-C344 = CAP_NP: ANOVO DESCRIPTION: CAP;0.01U ,16V ,10% ,0402 ,X7R ,SMT; ANOVO PART NUMBER: 272043103201; Part Type: CCAP
R193 R224 = R_v2: ANOVO DESCRIPTION: RES;150 £¬1/16W £¬1% £¬0402 £¬SMT; ANOVO PART NUMBER: 271040151101; BACKSIDE: 0; DUMMY: Not stuff; Part Type: RESISTOR; SMT: YES
R491 = R_v2: ANOVO DESCRIPTION: RES;100 ,1/16W ,1% ,0402 ,SMT; ANOVO PART NUMBER: 271040101101
R501 = R_v2: ANOVO DESCRIPTION: RES;0 ,1/16W ,5% ,0402 ,SMT; ANOVO PART NUMBER: 271040000301; BACKCOMP: YES; BACKSIDE: YES; DUMMY: Not stuff; ID: 0; Part Type: RESISTOR; SMT: YES
R502 R516 = R_v2: ANOVO DESCRIPTION: RES;0 ,1/16W ,5% ,0402 ,SMT; ANOVO PART NUMBER: 271040000301; BACKCOMP: YES; BACKSIDE: YES; ID: 0; Part Type: RESISTOR; SMT: YES
R530 = R_v2: ANOVO DESCRIPTION: RES,0 ,1/8W ,5% ,0805 ,SMT; ANOVO PART NUMBER: 271002000301
U7-U10 U27 U44 U45 = DDR2_64M*8bit_60_5
U43 = DDR2_64M*8bit_60_5: Part Number: 1410001014
U46 = AT24C04: IC SMD AT24C02BN-10SU-1.8 EEPROM SOIC8; Part Number: 14S6340200001
PD7 PD8 = DIODE: ANOVO DESCRIPTION: DIODE;TCLL4148,100V,150MA,3.5*1.5MM,SMT; ANOVO PART NUMBER: 288104148001; BACKSIDE: 0; Part Type: FAST; SMT: YES; Datasheet: \\Rdserver\norcocis\datasheet\DIODE\vishay\LS4148.PDF
Q33 = MOSFET_N_3P: ANOVO DESCRIPTION: TRANS;2N7002,N-MOSFET,60V,500mA,SOT23; ANOVO PART NUMBER: 288227002001; BACKSIDE: 0; Part Type: MOSFET; SMT: YES
R173 R190 = R_v2: ANOVO DESCRIPTION: RES;1M ,1/16W ,5% ,0402 ,SMT; ANOVO PART NUMBER: 271040105301; BACKSIDE: 0; Part Type: RESISTOR; SMT: YES
U28 U42 = LMV358_0: W/O Socket 10/100M: 1310000033; W/O Socket Giga: 1310000033; W/Socket Giga: 1310000033
U75 = 74AHC1G86GW_GATE

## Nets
3V_PS_ON: PQ23.3(G) U74.3(LGATE)
5V_PS_ON: PQ26.3(G) PQ31.3(G) U74.4(HGATE)
+1.8VSUS: C255.1 C298.1 C305.1 C306.1 C307.1 C308.1 C342.1 C343.1 C344.1 C345.1 C346.1 C347.1 C351.1 C352.1 C353.1 C354.1 C355.1 C356.1 C360.1 C361.1 C362.1 C363.1 C364.1 C366.1 C369.1 R193.2 U7.E1(VDD1) U7.E9(VDDQ1) U7.G1(VDDQ2) U7.G3(VDDQ3) U7.G7(VDDQ4) U7.G9(VDDQ5) U7.J1(VDDL) U7.J9(VDD2) U7.M9(VDD3) U7.R1(VDD4) U8.E1(VDD1) U8.E9(VDDQ1) U8.G1(VDDQ2) U8.G3(VDDQ3) U8.G7(VDDQ4) U8.G9(VDDQ5) U8.J1(VDDL) U8.J9(VDD2) U8.M9(VDD3) U8.R1(VDD4) U9.E1(VDD1) U9.E9(VDDQ1) U9.G1(VDDQ2) U9.G3(VDDQ3) U9.G7(VDDQ4) U9.G9(VDDQ5) U9.J1(VDDL) U9.J9(VDD2) U9.M9(VDD3) U9.R1(VDD4) U10.E1(VDD1) U10.E9(VDDQ1) U10.G1(VDDQ2) U10.G3(VDDQ3) U10.G7(VDDQ4) U10.G9(VDDQ5) U10.J1(VDDL) U10.J9(VDD2) U10.M9(VDD3) U10.R1(VDD4) U27.E1(VDD1) U27.E9(VDDQ1) U27.G1(VDDQ2) U27.G3(VDDQ3) U27.G7(VDDQ4) U27.G9(VDDQ5) U27.J1(VDDL) U27.J9(VDD2) U27.M9(VDD3) U27.R1(VDD4) U43.E1(VDD1) U43.E9(VDDQ1) U43.G1(VDDQ2) U43.G3(VDDQ3) U43.G7(VDDQ4) U43.G9(VDDQ5) U43.J1(VDDL) U43.J9(VDD2) U43.M9(VDD3) U43.R1(VDD4) U44.E1(VDD1) U44.E9(VDDQ1) U44.G1(VDDQ2) U44.G3(VDDQ3) U44.G7(VDDQ4) U44.G9(VDDQ5) U44.J1(VDDL) U44.J9(VDD2) U44.M9(VDD3) U44.R1(VDD4) U45.E1(VDD1) U45.E9(VDDQ1) U45.G1(VDDQ2) U45.G3(VDDQ3) U45.G7(VDDQ4) U45.G9(VDDQ5) U45.J1(VDDL) U45.J9(VDD2) U45.M9(VDD3) U45.R1(VDD4) ; also on sheet 9 11 12 14 21 32 33 39
+2.5V: C397.2 C534.2 FB32.2 FB34.2 R266.2 R641.1 R642.1 U34.5(Vout)
+3V: C158.1 C546.2 C3911.1 D17.2 FB31.2 FB33.1 PQ23.4(S) R627.2 R628.2 U34.1(Vin) U34.3(ON/#OFF) ; also on sheet 4 9 10 12 15 16 17 18 19 20 21 22 23 24 25 26 27 28 31 32 41
+3V_DUAL: C45.1 C405.1 C446.1 C565.2 PC459.1 PQ23.1(D1) PQ23.2(D2) PQ23.5(D5) PQ23.6(D6) PR485.2 Q862.4(VO) R500.2 U25.2(VCC) U41.5(VCC) U46.8(VCC) ; also on sheet 14 15 16 17 18 19 20 21 26 31 33 40 41
+5V: C553.2 PC45.1 PQ26.4(S) PQ31.4(S) R246.2 R264.2 R265.2 R447.2 ; also on sheet 18 21 22 23 24 25 26 27 29 30 31 32 33 40
+5V_CPCI: POWER_SEL1.1 PQ17.1(S1) PQ17.2(S2) PQ17.3(S3) ; also on sheet 27
+5V_DUAL: C552.2 PC457.1 PC458.1 PQ17.5(D) PQ26.1(D1) PQ26.2(D2) PQ26.5(D5) PQ26.6(D6) PQ31.1(D1) PQ31.2(D2) PQ31.5(D5) PQ31.6(D6) PQ82.2(Source) Q862.3(VI) U74.1(VCC) ; also on sheet 18 21 25 27 30 31 33
+5VSB: POWER_SEL1.2 PQ82.3(Drain) R295.1 R296.1 R448.1 R450.1 U75.5(VCC) ; also on sheet 32
+5VSB1: POWER_SEL1.3 ; also on sheet 30
+5VSB_GATE: PQ82.1(GATE) UR18.1
+12V_CPCI: UR17.2 UR18.2 ; also on sheet 21 24 25 26 27 32
+12V_GATE: C164.2 PQ17.4(G) R154.2 UR17.1
AVDD: C478.2 C535.2 C536.2 C537.2 FB32.1 U18.36(AVDD) U18.42(AVDD2) U18.48(AVDD3)
DVDD: C376.2 C543.2 C544.2 FB34.1 U18.12(DVDD) U18.28(DVDD2)
GND: C45.2 C158.2 C164.1 C167.1 C187.1 C255.2 C256.2 C298.2 C305.2 C306.2 C307.2 C308.2 C342.2 C343.2 C344.2 C345.2 C346.2 C347.2 C350.2 C351.2 C352.2 C353.2 C354.2 C355.2 C356.2 C357.2 C360.2 C361.2 C362.2 C363.2 C364.2 C366.2 C369.2 C370.2 C371.2 C372.2 C373.2 C374.2 C376.1 C394.2 C395.2 C397.1 C400.2 C405.2 C446.2 C477.1 C478.1 C509.2 C534.1 C535.1 C536.1 C537.1 C540.1 C541.1 C542.2 C543.1 C544.1 C546.1 C552.1 C553.1 C559.1 C565.1 C588.2 C589.2 C590.2 C591.2 C592.2 C593.2 C594.2 C595.2 C3911.2 C3922.2 D17.1 PC45.2 PC457.2 PC458.2 PC459.2 PQ29.2(E) PQ30.2(E) PR487.1 Q33.2(SOURCE) R154.1 R224.2 R268.1 R457.1 R501.1 U7.E3(VSS1) U7.E7(VSSQ1) U7.F2(VSSQ2) U7.F8(VSSQ3) U7.H2(VSSQ4) U7.H8(VSSQ5) U7.J3(VSS2) U7.J7(VSSDL) U7.N1(VSS3) U7.P9(VSS4) U8.E3(VSS1) U8.E7(VSSQ1) U8.F2(VSSQ2) U8.F8(VSSQ3) U8.H2(VSSQ4) U8.H8(VSSQ5) U8.J3(VSS2) U8.J7(VSSDL) U8.N1(VSS3) U8.P9(VSS4) U9.E3(VSS1) U9.E7(VSSQ1) U9.F2(VSSQ2) U9.F8(VSSQ3) U9.H2(VSSQ4) U9.H8(VSSQ5) U9.J3(VSS2) U9.J7(VSSDL) U9.N1(VSS3) U9.P9(VSS4) U10.E3(VSS1) U10.E7(VSSQ1) U10.F2(VSSQ2) U10.F8(VSSQ3) U10.H2(VSSQ4) U10.H8(VSSQ5) U10.J3(VSS2) U10.J7(VSSDL) U10.N1(VSS3) U10.P9(VSS4) U18.6(AGND_PLL) U18.7(DGND) U18.18(TGND) U18.24(TGND2) U18.30(DGND2) U18.31(AGND) U18.39(AGND2) U18.45(AGND3) U18.49(RESERVED4) U25.3(GND) U27.E3(VSS1) U27.E7(VSSQ1) U27.F2(VSSQ2) U27.F8(VSSQ3) U27.H2(VSSQ4) U27.H8(VSSQ5) U27.J3(VSS2) U27.J7(VSSDL) U27.N1(VSS3) U27.P9(VSS4) U28.2(S2) U28.5(S1) U34.2(GND) U41.3(GND) U42.2(S2) U42.5(S1) U43.E3(VSS1) U43.E7(VSSQ1) U43.F2(VSSQ2) U43.F8(VSSQ3) U43.H2(VSSQ4) U43.H8(VSSQ5) U43.J3(VSS2) U43.J7(VSSDL) U43.N1(VSS3) U43.P9(VSS4) U44.E3(VSS1) U44.E7(VSSQ1) U44.F2(VSSQ2) U44.F8(VSSQ3) U44.H2(VSSQ4) U44.H8(VSSQ5) U44.J3(VSS2) U44.J7(VSSDL) U44.N1(VSS3) U44.P9(VSS4) U45.E3(VSS1) U45.E7(VSSQ1) U45.F2(VSSQ2) U45.F8(VSSQ3) U45.H2(VSSQ4) U45.H8(VSSQ5) U45.J3(VSS2) U45.J7(VSSDL) U45.N1(VSS3) U45.P9(VSS4) U46.1(A0) U46.3(A2) U46.4(GND) U46.7(WP) U74.2(GND) U75.3(GND) ; also on sheet 4 5 6 7 9 10 11 12 13 14 15 16 17 18 19 20 21 22 23 24 25 26 27 28 29 30 31 32 33 39 40 41
1084ADJ1: PR485.1 PR487.2 Q862.1(ADJ)
BSCAN: R268.2 U18.26(BSCAN)
CGCLK_SMB: R516.1 ; also on sheet 4 14
CGDAT_SMB: R502.1 ; also on sheet 4 14
DELAY_4S: R295.2 U28.4(D2) U75.1(INB)
DELAY_6S: R448.2 U42.4(D2) U75.2(INA)
DIMM_VREF_B: C256.1 C370.1 C371.1 C372.1 C373.1 C374.1 C394.1 C395.1 C400.1 R193.1 R224.1 R530.1 U7.J2(VREF) U8.J2(VREF) U9.J2(VREF) U10.J2(VREF) U27.J2(VREF) U43.J2(VREF) U44.J2(VREF) U45.J2(VREF) ; also on sheet 39
DVI_A_CLK: U18.14(TLC) ; also on sheet 30
DVI_A_CLK#: U18.13(TLC#) ; also on sheet 30
DVI_A_HPD: R267.2 ; also on sheet 30
DVI_A_TX0: U18.17(TDC0) ; also on sheet 30
DVI_A_TX0#: U18.16(TDC0#) ; also on sheet 30
DVI_A_TX1: U18.20(TDC1) ; also on sheet 30
DVI_A_TX1#: U18.19(TDC1#) ; also on sheet 30
DVI_A_TX2: U18.23(TDC2) ; also on sheet 30
DVI_A_TX2#: U18.22(TDC2#) ; also on sheet 30
HPDET_C: PQ30.3(C) R628.1 U18.29(HPDET)
M_B_A0: RN6.6(R32) RP52.5 ; also on sheet 8
M_B_A1: RN12.6(R32) RP62.5 ; also on sheet 8
M_B_A2: RN12.8(R42) RP62.7 ; also on sheet 8
M_B_A3: RN12.2(R12) RP62.1 ; also on sheet 8
M_B_A4: RN12.4(R22) RP62.3 ; also on sheet 8
M_B_A5: RN4.6(R32) RP53.5 ; also on sheet 8
M_B_A6: RN4.8(R42) RP53.7 ; also on sheet 8
M_B_A7: RN4.2(R12) RP53.1 ; also on sheet 8
M_B_A8: RN4.4(R22) RP53.3 ; also on sheet 8
M_B_A9: RN2.4(R22) RP63.3 ; also on sheet 8
M_B_A10: RN6.8(R42) RP52.7 ; also on sheet 8
M_B_A11: RN2.2(R12) RP63.1 ; also on sheet 8
M_B_A12: RN2.8(R42) RP63.7 ; also on sheet 8
M_B_A13: RN2.6(R32) RP63.5 ; also on sheet 8
M_B_BS#0: RN10.8(R42) RP66.7 ; also on sheet 8
M_B_BS#1: RN6.4(R22) RP52.3 ; also on sheet 8
M_B_BS#2: RN10.6(R32) RP66.5 ; also on sheet 8
M_B_CAS#: RN6.2(R12) RP52.1 ; also on sheet 8
M_B_DM0: R492.2 ; also on sheet 8
M_B_DM1: R493.2 ; also on sheet 8
M_B_DM2: R494.2 ; also on sheet 8
M_B_DM3: R495.2 ; also on sheet 8
M_B_DM4: R496.2 ; also on sheet 8
M_B_DM5: R497.2 ; also on sheet 8
M_B_DM6: R498.2 ; also on sheet 8
M_B_DM7: R499.2 ; also on sheet 8
M_B_DQ0: RP59.7 ; also on sheet 8
M_B_DQ1: RP59.5 ; also on sheet 8
M_B_DQ2: RP56.1 ; also on sheet 8
M_B_DQ3: RP56.7 ; also on sheet 8
M_B_DQ4: RP59.1 ; also on sheet 8
M_B_DQ5: RP59.3 ; also on sheet 8
M_B_DQ6: RP56.3 ; also on sheet 8
M_B_DQ7: RP56.5 ; also on sheet 8
M_B_DQ8: RP60.3 ; also on sheet 8
M_B_DQ9: RP60.1 ; also on sheet 8
M_B_DQ10: RP60.7 ; also on sheet 8
M_B_DQ11: RP61.3 ; also on sheet 8
M_B_DQ12: RP61.1 ; also on sheet 8
M_B_DQ13: RP60.5 ; also on sheet 8
M_B_DQ14: RP61.5 ; also on sheet 8
M_B_DQ15: RP61.7 ; also on sheet 8
M_B_DQ16: RP68.7 ; also on sheet 8
M_B_DQ17: RP68.3 ; also on sheet 8
M_B_DQ18: RP67.3 ; also on sheet 8
M_B_DQ19: RP67.5 ; also on sheet 8
M_B_DQ20: RP68.5 ; also on sheet 8
M_B_DQ21: RP68.1 ; also on sheet 8
M_B_DQ22: RP67.7 ; also on sheet 8
M_B_DQ23: RP67.1 ; also on sheet 8
M_B_DQ24: RP51.5 ; also on sheet 8
M_B_DQ25: RP51.3 ; also on sheet 8
M_B_DQ26: RP51.1 ; also on sheet 8
M_B_DQ27: RP51.7 ; also on sheet 8
M_B_DQ28: RP50.1 ; also on sheet 8
M_B_DQ29: RP50.7 ; also on sheet 8
M_B_DQ30: RP50.5 ; also on sheet 8
M_B_DQ31: RP50.3 ; also on sheet 8
M_B_DQ32: RP58.1 ; also on sheet 8
M_B_DQ33: RP58.7 ; also on sheet 8
M_B_DQ34: RP57.7 ; also on sheet 8
M_B_DQ35: RP57.1 ; also on sheet 8
M_B_DQ36: RP58.5 ; also on sheet 8
M_B_DQ37: RP58.3 ; also on sheet 8
M_B_DQ38: RP57.3 ; also on sheet 8
M_B_DQ39: RP57.5 ; also on sheet 8
M_B_DQ40: RP64.5 ; also on sheet 8
M_B_DQ41: RP64.3 ; also on sheet 8
M_B_DQ42: RP64.1 ; also on sheet 8
M_B_DQ43: RP64.7 ; also on sheet 8
M_B_DQ44: RP65.1 ; also on sheet 8
M_B_DQ45: RP65.3 ; also on sheet 8
M_B_DQ46: RP65.7 ; also on sheet 8
M_B_DQ47: RP65.5 ; also on sheet 8
M_B_DQ48: RP49.1 ; also on sheet 8
M_B_DQ49: RP49.7 ; also on sheet 8
M_B_DQ50: RP48.3 ; also on sheet 8
M_B_DQ51: RP48.7 ; also on sheet 8
M_B_DQ52: RP49.3 ; also on sheet 8
M_B_DQ53: RP49.5 ; also on sheet 8
M_B_DQ54: RP48.1 ; also on sheet 8
M_B_DQ55: RP48.5 ; also on sheet 8
M_B_DQ56: RP54.5 ; also on sheet 8
M_B_DQ57: RP54.3 ; also on sheet 8
M_B_DQ58: RP54.7 ; also on sheet 8
M_B_DQ59: RP54.1 ; also on sheet 8
M_B_DQ60: RP55.1 ; also on sheet 8
M_B_DQ61: RP55.7 ; also on sheet 8
M_B_DQ62: RP55.5 ; also on sheet 8
M_B_DQ63: RP55.3 ; also on sheet 8
M_B_DQS0: R490.2 ; also on sheet 8
M_B_DQS1: R489.2 ; also on sheet 8
M_B_DQS2: R171.2 ; also on sheet 8
M_B_DQS3: R225.2 ; also on sheet 8
M_B_DQS4: R477.2 ; also on sheet 8
M_B_DQS5: R480.2 ; also on sheet 8
M_B_DQS6: R231.2 ; also on sheet 8
M_B_DQS7: R230.2 ; also on sheet 8
M_B_DQS#0: R487.2 ; also on sheet 8
M_B_DQS#1: R488.2 ; also on sheet 8
M_B_DQS#2: R482.2 ; also on sheet 8
M_B_DQS#3: R481.2 ; also on sheet 8
M_B_DQS#4: R486.2 ; also on sheet 8
M_B_DQS#5: R485.2 ; also on sheet 8
M_B_DQS#6: R483.2 ; also on sheet 8
M_B_DQS#7: R484.2 ; also on sheet 8
M_B_RAS#: RN10.2(R12) RP66.1 ; also on sheet 8
M_B_WE#: RN10.4(R22) RP66.3 ; also on sheet 8
M_CKE2: R128.1 R549.1 ; also on sheet 9
M_CKE3: R153.1 R552.1 ; also on sheet 9
M_CLK_DDR2: C271.2 R491.1 U7.J8(CK) U9.J8(CK) U27.J8(CK) U43.J8(CK) ; also on sheet 9 39
M_CLK_DDR2#: C271.1 R491.2 U7.K8(~{CK}) U9.K8(~{CK}) U27.K8(~{CK}) U43.K8(~{CK}) ; also on sheet 9 39
M_CLK_DDR3: U8.J8(CK) U10.J8(CK) U44.J8(CK) U45.J8(CK) ; also on sheet 9 39
M_CLK_DDR3#: U8.K8(~{CK}) U10.K8(~{CK}) U44.K8(~{CK}) U45.K8(~{CK}) ; also on sheet 9 39
M_CS#2: R125.1 R557.1 ; also on sheet 9
M_CS#3: R121.1 R558.1 ; also on sheet 9
M_ODT2: R126.1 R555.1 ; also on sheet 9
M_ODT3: R123.1 R556.1 ; also on sheet 9
PEG_RXN1: C538.1 ; also on sheet 10
PEG_RXP1: C539.1 ; also on sheet 10
PEG_TXN0: U18.38(SDVO_R-) ; also on sheet 10
PEG_TXN1: U18.41(SDVO_G-) ; also on sheet 10
PEG_TXN2: U18.44(SDVO_B-) ; also on sheet 10
PEG_TXN3: U18.47(SDVO_CLK-) ; also on sheet 10
PEG_TXP0: U18.37(SDVO_R+) ; also on sheet 10
PEG_TXP1: U18.40(SDVO_G+) ; also on sheet 10
PEG_TXP2: U18.43(SDVO_B+) ; also on sheet 10
PEG_TXP3: U18.46(SDVO_CLK+) ; also on sheet 10
PLTRST#: U18.2(RESET#) ; also on sheet 16 19 20 21 24
R_B_A0: RP52.6 U7.M8(A0) U8.M8(A0) U9.M8(A0) U10.M8(A0) U27.M8(A0) U43.M8(A0) U44.M8(A0) U45.M8(A0) ; also on sheet 39
R_B_A1: RP62.6 U7.M3(A1) U8.M3(A1) U9.M3(A1) U10.M3(A1) U27.M3(A1) U43.M3(A1) U44.M3(A1) U45.M3(A1) ; also on sheet 39
R_B_A2: RP62.8 U7.M7(A2) U8.M7(A2) U9.M7(A2) U10.M7(A2) U27.M7(A2) U43.M7(A2) U44.M7(A2) U45.M7(A2) ; also on sheet 39
R_B_A3: RP62.2 U7.N2(A3) U8.N2(A3) U9.N2(A3) U10.N2(A3) U27.N2(A3) U43.N2(A3) U44.N2(A3) U45.N2(A3) ; also on sheet 39
R_B_A4: RP62.4 U7.N8(A4) U8.N8(A4) U9.N8(A4) U10.N8(A4) U27.N8(A4) U43.N8(A4) U44.N8(A4) U45.N8(A4) ; also on sheet 39
R_B_A5: RP53.6 U7.N3(A5) U8.N3(A5) U9.N3(A5) U10.N3(A5) U27.N3(A5) U43.N3(A5) U44.N3(A5) U45.N3(A5) ; also on sheet 39
R_B_A6: RP53.8 U7.N7(A6) U8.N7(A6) U9.N7(A6) U10.N7(A6) U27.N7(A6) U43.N7(A6) U44.N7(A6) U45.N7(A6) ; also on sheet 39
R_B_A7: RP53.2 U7.P2(A7) U8.P2(A7) U9.P2(A7) U10.P2(A7) U27.P2(A7) U43.P2(A7) U44.P2(A7) U45.P2(A7) ; also on sheet 39
R_B_A8: RP53.4 U7.P8(A8) U8.P8(A8) U9.P8(A8) U10.P8(A8) U27.P8(A8) U43.P8(A8) U44.P8(A8) U45.P8(A8) ; also on sheet 39
R_B_A9: RP63.4 U7.P3(A9) U8.P3(A9) U9.P3(A9) U10.P3(A9) U27.P3(A9) U43.P3(A9) U44.P3(A9) U45.P3(A9) ; also on sheet 39
R_B_A10: RP52.8 U7.M2(A10) U8.M2(A10) U9.M2(A10) U10.M2(A10) U27.M2(A10) U43.M2(A10) U44.M2(A10) U45.M2(A10) ; also on sheet 39
R_B_A11: RP63.2 U7.P7(A11) U8.P7(A11) U9.P7(A11) U10.P7(A11) U27.P7(A11) U43.P7(A11) U44.P7(A11) U45.P7(A11) ; also on sheet 39
R_B_A12: RP63.8 U7.R2(A12) U8.R2(A12) U9.R2(A12) U10.R2(A12) U27.R2(A12) U43.R2(A12) U44.R2(A12) U45.R2(A12) ; also on sheet 39
R_B_A13: RP63.6 U7.R8(A13) U8.R8(A13) U9.R8(A13) U10.R8(A13) U27.R8(A13) U43.R8(A13) U44.R8(A13) U45.R8(A13) ; also on sheet 39
R_B_BS#0: RP66.8 U7.L2(BA0) U8.L2(BA0) U9.L2(BA0) U10.L2(BA0) U27.L2(BA0) U43.L2(BA0) U44.L2(BA0) U45.L2(BA0) ; also on sheet 39
R_B_BS#1: RP52.4 U7.L3(BA1) U8.L3(BA1) U9.L3(BA1) U10.L3(BA1) U27.L3(BA1) U43.L3(BA1) U44.L3(BA1) U45.L3(BA1) ; also on sheet 39
R_B_BS#2: RP66.6 U7.L1(BA2) U8.L1(BA2) U9.L1(BA2) U10.L1(BA2) U27.L1(BA2) U43.L1(BA2) U44.L1(BA2) U45.L1(BA2) ; also on sheet 39
R_B_CAS#: RP52.2 U7.L7(~{CAS}) U8.L7(~{CAS}) U9.L7(~{CAS}) U10.L7(~{CAS}) U27.L7(~{CAS}) U43.L7(~{CAS}) U44.L7(~{CAS}) U45.L7(~{CAS}) ; also on sheet 39
R_B_CKE2: R549.2 U7.K2(CKE) U8.K2(CKE) U9.K2(CKE) U10.K2(CKE) U27.K2(CKE) U43.K2(CKE) U44.K2(CKE) U45.K2(CKE)
R_B_CKE3: R552.2 ; also on sheet 39
R_B_CS#2: R557.2 U7.L8(~{CS}) U8.L8(~{CS}) U9.L8(~{CS}) U10.L8(~{CS}) U27.L8(~{CS}) U43.L8(~{CS}) U44.L8(~{CS}) U45.L8(~{CS})
R_B_CS#3: R558.2 ; also on sheet 39
R_B_DM0: R492.1 U43.F3(DM/RDQS) ; also on sheet 39
R_B_DM1: R493.1 U7.F3(DM/RDQS) ; also on sheet 39
R_B_DM2: R494.1 U9.F3(DM/RDQS) ; also on sheet 39
R_B_DM3: R495.1 U27.F3(DM/RDQS) ; also on sheet 39
R_B_DM4: R496.1 U8.F3(DM/RDQS) ; also on sheet 39
R_B_DM5: R497.1 U45.F3(DM/RDQS) ; also on sheet 39
R_B_DM6: R498.1 U10.F3(DM/RDQS) ; also on sheet 39
R_B_DM7: R499.1 U44.F3(DM/RDQS) ; also on sheet 39
R_B_DQ0: RP59.8 U43.H9(DQ5) ; also on sheet 39
R_B_DQ1: RP59.6 U43.H7(DQ2) ; also on sheet 39
R_B_DQ2: RP56.2 U43.H1(DQ4) ; also on sheet 39
R_B_DQ3: RP56.8 U43.F1(DQ6) ; also on sheet 39
R_B_DQ4: RP59.2 U43.F9(DQ7) ; also on sheet 39
R_B_DQ5: RP59.4 U43.G8(DQ0) ; also on sheet 39
R_B_DQ6: RP56.4 U43.H3(DQ3) ; also on sheet 39
R_B_DQ7: RP56.6 U43.G2(DQ1) ; also on sheet 39
R_B_DQ8: RP60.4 U7.G8(DQ0) ; also on sheet 39
R_B_DQ9: RP60.2 U7.F9(DQ7) ; also on sheet 39
R_B_DQ10: RP60.8 U7.H9(DQ5) ; also on sheet 39
R_B_DQ11: RP61.4 U7.H3(DQ3) ; also on sheet 39
R_B_DQ12: RP61.2 U7.H1(DQ4) ; also on sheet 39
R_B_DQ13: RP60.6 U7.H7(DQ2) ; also on sheet 39
R_B_DQ14: RP61.6 U7.G2(DQ1) ; also on sheet 39
R_B_DQ15: RP61.8 U7.F1(DQ6) ; also on sheet 39
R_B_DQ16: RP68.8 U9.H9(DQ5) ; also on sheet 39
R_B_DQ17: RP68.4 U9.G8(DQ0) ; also on sheet 39
R_B_DQ18: RP67.4 U9.H3(DQ3) ; also on sheet 39
R_B_DQ19: RP67.6 U9.G2(DQ1) ; also on sheet 39
R_B_DQ20: RP68.6 U9.H7(DQ2) ; also on sheet 39
R_B_DQ21: RP68.2 U9.F9(DQ7) ; also on sheet 39
R_B_DQ22: RP67.8 U9.F1(DQ6) ; also on sheet 39
R_B_DQ23: RP67.2 U9.H1(DQ4) ; also on sheet 39
R_B_DQ24: RP51.6 U27.H7(DQ2) ; also on sheet 39
R_B_DQ25: RP51.4 U27.G8(DQ0) ; also on sheet 39
R_B_DQ26: RP51.2 U27.F9(DQ7) ; also on sheet 39
R_B_DQ27: RP51.8 U27.H9(DQ5) ; also on sheet 39
R_B_DQ28: RP50.2 U27.H1(DQ4) ; also on sheet 39
R_B_DQ29: RP50.8 U27.F1(DQ6) ; also on sheet 39
R_B_DQ30: RP50.6 U27.G2(DQ1) ; also on sheet 39
R_B_DQ31: RP50.4 U27.H3(DQ3) ; also on sheet 39
R_B_DQ32: RP58.2 U8.F9(DQ7) ; also on sheet 39
R_B_DQ33: RP58.8 U8.H9(DQ5) ; also on sheet 39
R_B_DQ34: RP57.8 U8.F1(DQ6) ; also on sheet 39
R_B_DQ35: RP57.2 U8.H1(DQ4) ; also on sheet 39
R_B_DQ36: RP58.6 U8.H7(DQ2) ; also on sheet 39
R_B_DQ37: RP58.4 U8.G8(DQ0) ; also on sheet 39
R_B_DQ38: RP57.4 U8.H3(DQ3) ; also on sheet 39
R_B_DQ39: RP57.6 U8.G2(DQ1) ; also on sheet 39
R_B_DQ40: RP64.6 U45.H7(DQ2) ; also on sheet 39
R_B_DQ41: RP64.4 U45.G8(DQ0) ; also on sheet 39
R_B_DQ42: RP64.2 U45.F9(DQ7) ; also on sheet 39
R_B_DQ43: RP64.8 U45.H9(DQ5) ; also on sheet 39
R_B_DQ44: RP65.2 U45.H1(DQ4) ; also on sheet 39
R_B_DQ45: RP65.4 U45.H3(DQ3) ; also on sheet 39
R_B_DQ46: RP65.8 U45.F1(DQ6) ; also on sheet 39
R_B_DQ47: RP65.6 U45.G2(DQ1) ; also on sheet 39
R_B_DQ48: RP49.2 U10.F9(DQ7) ; also on sheet 39
R_B_DQ49: RP49.8 U10.H9(DQ5) ; also on sheet 39
R_B_DQ50: RP48.4 U10.H3(DQ3) ; also on sheet 39
R_B_DQ51: RP48.8 U10.F1(DQ6) ; also on sheet 39
R_B_DQ52: RP49.4 U10.G8(DQ0) ; also on sheet 39
R_B_DQ53: RP49.6 U10.H7(DQ2) ; also on sheet 39
R_B_DQ54: RP48.2 U10.H1(DQ4) ; also on sheet 39
R_B_DQ55: RP48.6 U10.G2(DQ1) ; also on sheet 39
R_B_DQ56: RP54.6 U44.H7(DQ2) ; also on sheet 39
R_B_DQ57: RP54.4 U44.G8(DQ0) ; also on sheet 39
R_B_DQ58: RP54.8 U44.H9(DQ5) ; also on sheet 39
R_B_DQ59: RP54.2 U44.F9(DQ7) ; also on sheet 39
R_B_DQ60: RP55.2 U44.H1(DQ4) ; also on sheet 39
R_B_DQ61: RP55.8 U44.F1(DQ6) ; also on sheet 39
R_B_DQ62: RP55.6 U44.G2(DQ1) ; also on sheet 39
R_B_DQ63: RP55.4 U44.H3(DQ3) ; also on sheet 39
R_B_DQS0: R490.1 U43.F7(DQS) ; also on sheet 39
R_B_DQS1: R489.1 U7.F7(DQS) ; also on sheet 39
R_B_DQS2: R171.1 U9.F7(DQS) ; also on sheet 39
R_B_DQS3: R225.1 U27.F7(DQS) ; also on sheet 39
R_B_DQS4: R477.1 U8.F7(DQS) ; also on sheet 39
R_B_DQS5: R480.1 U45.F7(DQS) ; also on sheet 39
R_B_DQS6: R231.1 U10.F7(DQS) ; also on sheet 39
R_B_DQS7: R230.1 U44.F7(DQS) ; also on sheet 39
R_B_DQS#0: R487.1 U43.E8(~{DQS}) ; also on sheet 39
R_B_DQS#1: R488.1 U7.E8(~{DQS}) ; also on sheet 39
R_B_DQS#2: R482.1 U9.E8(~{DQS}) ; also on sheet 39
R_B_DQS#3: R481.1 U27.E8(~{DQS}) ; also on sheet 39
R_B_DQS#4: R486.1 U8.E8(~{DQS}) ; also on sheet 39
R_B_DQS#5: R485.1 U45.E8(~{DQS}) ; also on sheet 39
R_B_DQS#6: R483.1 U10.E8(~{DQS}) ; also on sheet 39
R_B_DQS#7: R484.1 U44.E8(~{DQS}) ; also on sheet 39
R_B_ODT2: R555.2 U7.K9(ODT) U8.K9(ODT) U9.K9(ODT) U10.K9(ODT) U27.K9(ODT) U43.K9(ODT) U44.K9(ODT) U45.K9(ODT)
R_B_ODT3: R556.2 ; also on sheet 39
R_B_RAS#: RP66.2 U7.K7(~{RAS}) U8.K7(~{RAS}) U9.K7(~{RAS}) U10.K7(~{RAS}) U27.K7(~{RAS}) U43.K7(~{RAS}) U44.K7(~{RAS}) U45.K7(~{RAS}) ; also on sheet 39
R_B_WE#: RP66.4 U7.K3(~{WE}) U8.K3(~{WE}) U9.K3(~{WE}) U10.K3(~{WE}) U27.K3(~{WE}) U43.K3(~{WE}) U44.K3(~{WE}) U45.K3(~{WE}) ; also on sheet 39
RSMRST#: R356.2 U28.1(G1) U42.1(G1) ; also on sheet 17 19 20 21 41
SC_PROM: R246.1 U18.9(SC_PROM)
SCLDDC: C357.1 R265.1 U18.11(SC_DDC) ; also on sheet 30
SD_PROM: R447.1 U18.8(SD_PROM)
SDADDC: C350.1 R264.1 U18.10(SD_DDC) ; also on sheet 30
SDVO_CTRL_CLK: R642.2 U18.4(SPC) ; also on sheet 9
SDVO_CTRL_DAT: C559.2 R641.2 U18.5(SPD) ; also on sheet 9
SDVO_INT+: C539.2 U18.32(SDVO_INT+)
SDVO_INT-: C538.2 U18.33(SDVO_INT-)
SIOBTN: PWR_ON.2 ; also on sheet 17 21
SLP_S3#: U41.1(INB) U41.2(INA) ; also on sheet 17 21 32 33
SMB_CLK_SPD: R516.2 U46.6(SCL)
SMB_DAT_SPD: R502.2 U46.5(SDA)
SMDDR_VREF: R530.2 ; also on sheet 9 14 33
SMDDR_VTERM: C588.1 C589.1 C590.1 C591.1 C592.1 C593.1 C594.1 C595.1 R121.2 R123.2 R125.2 R126.2 R128.2 R153.2 RN2.1(R11) RN2.3(R21) RN2.5(R31) RN2.7(R41) RN4.1(R11) RN4.3(R21) RN4.5(R31) RN4.7(R41) RN6.1(R11) RN6.3(R21) RN6.5(R31) RN6.7(R41) RN10.1(R11) RN10.3(R21) RN10.5(R31) RN10.7(R41) RN12.1(R11) RN12.3(R21) RN12.5(R31) RN12.7(R41) ; also on sheet 14 32 33
VSWING: R457.2 U18.25(VSWING)
N99324846: C477.2 C540.2 C541.2 FB33.2 U18.15(TVDD) U18.21(TVDD2)
N99325054: PQ29.3(C) PQ30.1(B) R627.1
N99325538: C3922.1 U34.4(Bypass)
N99325608: D17.3 PQ29.1(B) R267.1
N99325851: C509.1 C542.1 FB31.1 U18.1(AVDD_PLL)
N99325869: R266.1 U18.3(AS)
N104354467: R356.1 U25.1(~{RST})
N105969207: R307.2 U74.5(EN)
N106902315: TH6.1 TH6.2 TH6.3 TH6.5 TH6.6 TH6.7 TH6.8
N106917299: TH7.1 TH7.2 TH7.3 TH7.5 TH7.6 TH7.7 TH7.8
N106920258: TH8.1 TH8.2 TH8.3 TH8.5 TH8.6 TH8.7 TH8.8
N106923227: TH5.1 TH5.2 TH5.3 TH5.5 TH5.6 TH5.7 TH5.8
N106985869: TH9.1 TH9.2 TH9.3 TH9.5 TH9.6 TH9.7 TH9.8
N107003076: TH10.1 TH10.2 TH10.3 TH10.5 TH10.6 TH10.7 TH10.8
N107055394: TH11.1 TH11.2 TH11.3 TH11.5 TH11.6 TH11.7 TH11.8
N107357808: R307.1 U41.4(OUT)
N110244303: C167.2 PD7.2(C) R173.2 U28.3(G2)
N110244657: PWR_ON.1 Q33.3(DRAIN)
N110325926: Q33.1(GATE) U75.4(OUTY)
N110356283: PD7.1(A) R173.1 R296.2 U28.6(D1)
N110368237: C187.2 PD8.2(C) R190.2 U42.3(G2)
N110368291: PD8.1(A) R190.1 R450.2 U42.6(D1)
N110408617: R500.1 R501.2 U46.2(A1)

Not connected (* = marked no-connect by the designer): PWR_ON 3*; TH1 1*; TH2 1*; TH3 1*; TH4 1*; TH5 4*; TH6 4*; TH7 4*; TH8 4*; TH9 4*; TH10 4*; TH11 4*; U7 E2(NU/~{RDQS}) R3(NC9) R7(NC10); U8 E2(NU/~{RDQS}) R3(NC9) R7(NC10); U9 E2(NU/~{RDQS}) R3(NC9) R7(NC10); U10 E2(NU/~{RDQS}) R3(NC9) R7(NC10); U18 27(RESERVED)* 34(RESERVED2)* 35(RESERVED3)*; U27 E2(NU/~{RDQS}) R3(NC9) R7(NC10); U43 E2(NU/~{RDQS}) R3(NC9) R7(NC10); U44 E2(NU/~{RDQS}) R3(NC9) R7(NC10); U45 E2(NU/~{RDQS}) R3(NC9) R7(NC10)

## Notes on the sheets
sheet 34
- If Q862 is adjustalbe regulator,stuff
  R225:182ohm,R224:300ohm,PN is
  271071182011,271071301301
- DUAL POWER
- 1-2
- AT
- 2-3
- ATX
- POWER SELECT
- S0 POWER SWITCH
- CENTER D=3.5mm
- 4 MTG D=3mm
- 2 MTG INTERNAL D=3mm
  OUTER D=7mm
- 4 MTG D=3.5mm
sheet 35
- I2C Address Select
- AS
- I2C Write
- I2C Read
- STATE
- HIGH
- 0x70(Default)
- 0x71(Default)
- LOW
- 0x72
- 0x73
sheet 38
- 0402
- 0402
- 0402
- SPD
- Default ADDRESS=010
